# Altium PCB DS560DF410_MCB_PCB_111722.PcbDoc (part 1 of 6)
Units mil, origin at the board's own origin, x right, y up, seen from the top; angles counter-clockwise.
Board outline 5500 x 5000 mil, 6 copper layers (Top Layer, L2_GND1, L3_SIG1, L4_PWR1, L5_GND2, Bottom Layer), stack 61.748 mil thick; 297 components, 231 nets, 1236 pads, 998 vias.
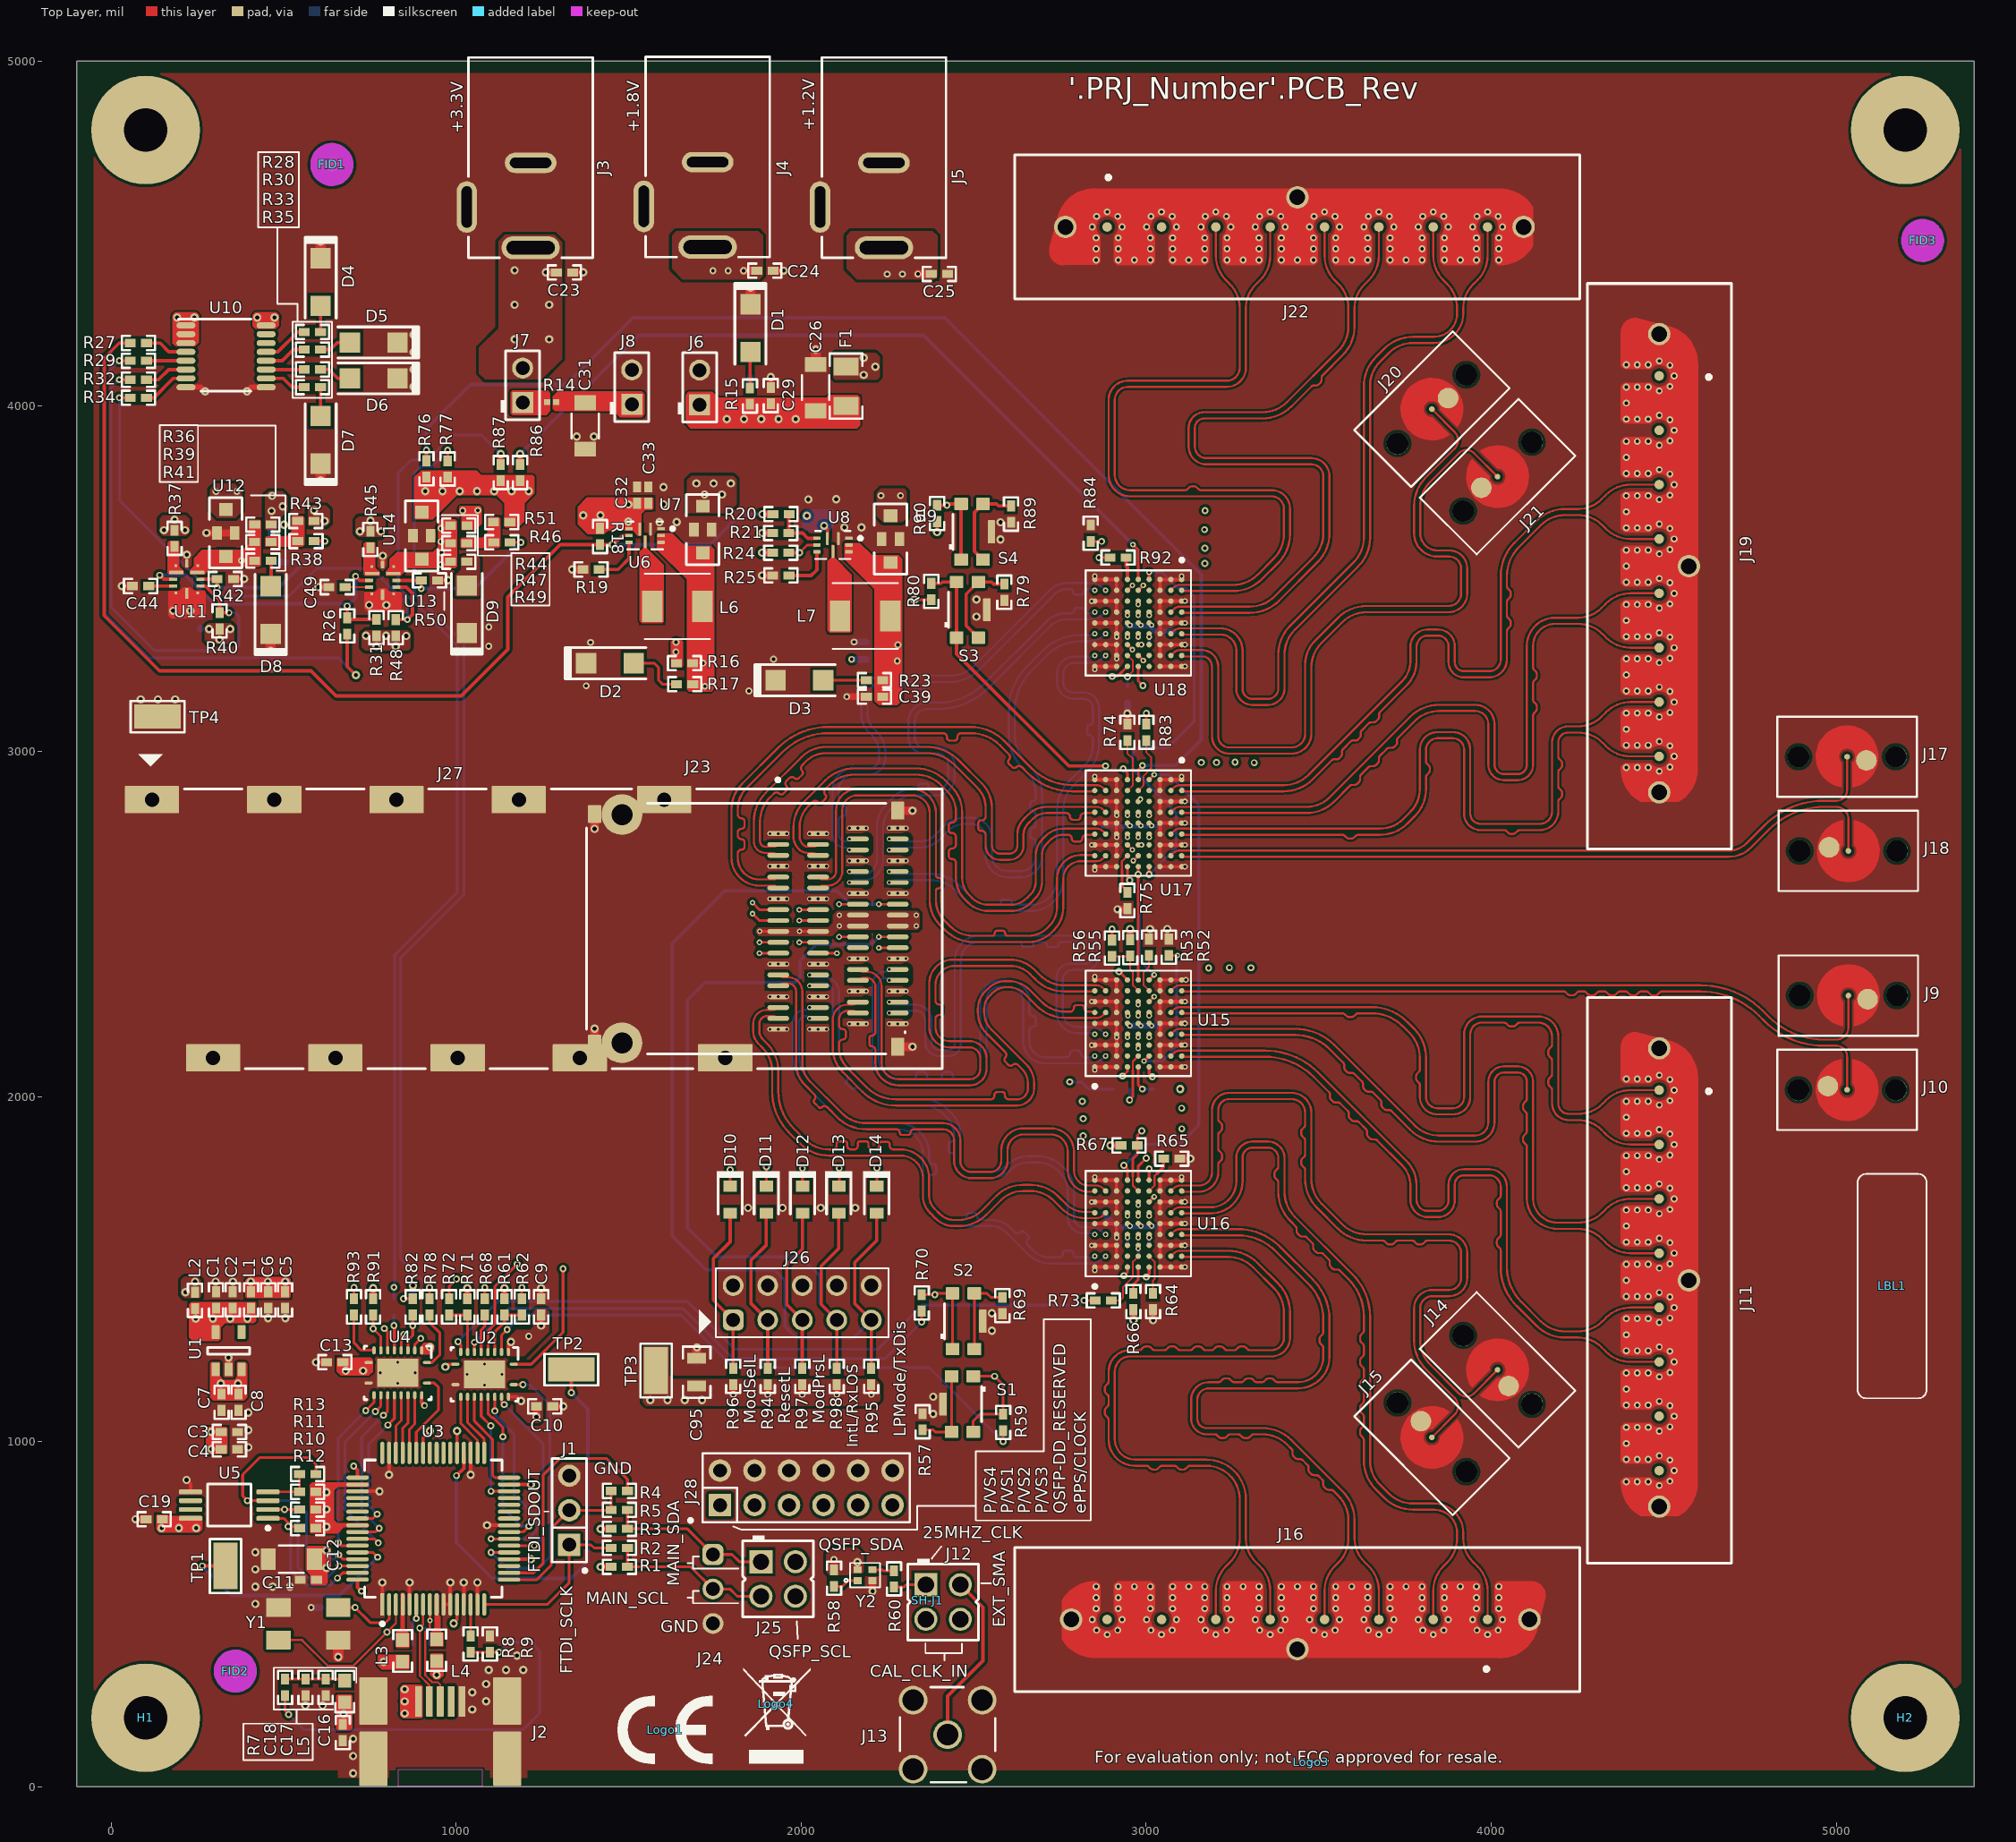
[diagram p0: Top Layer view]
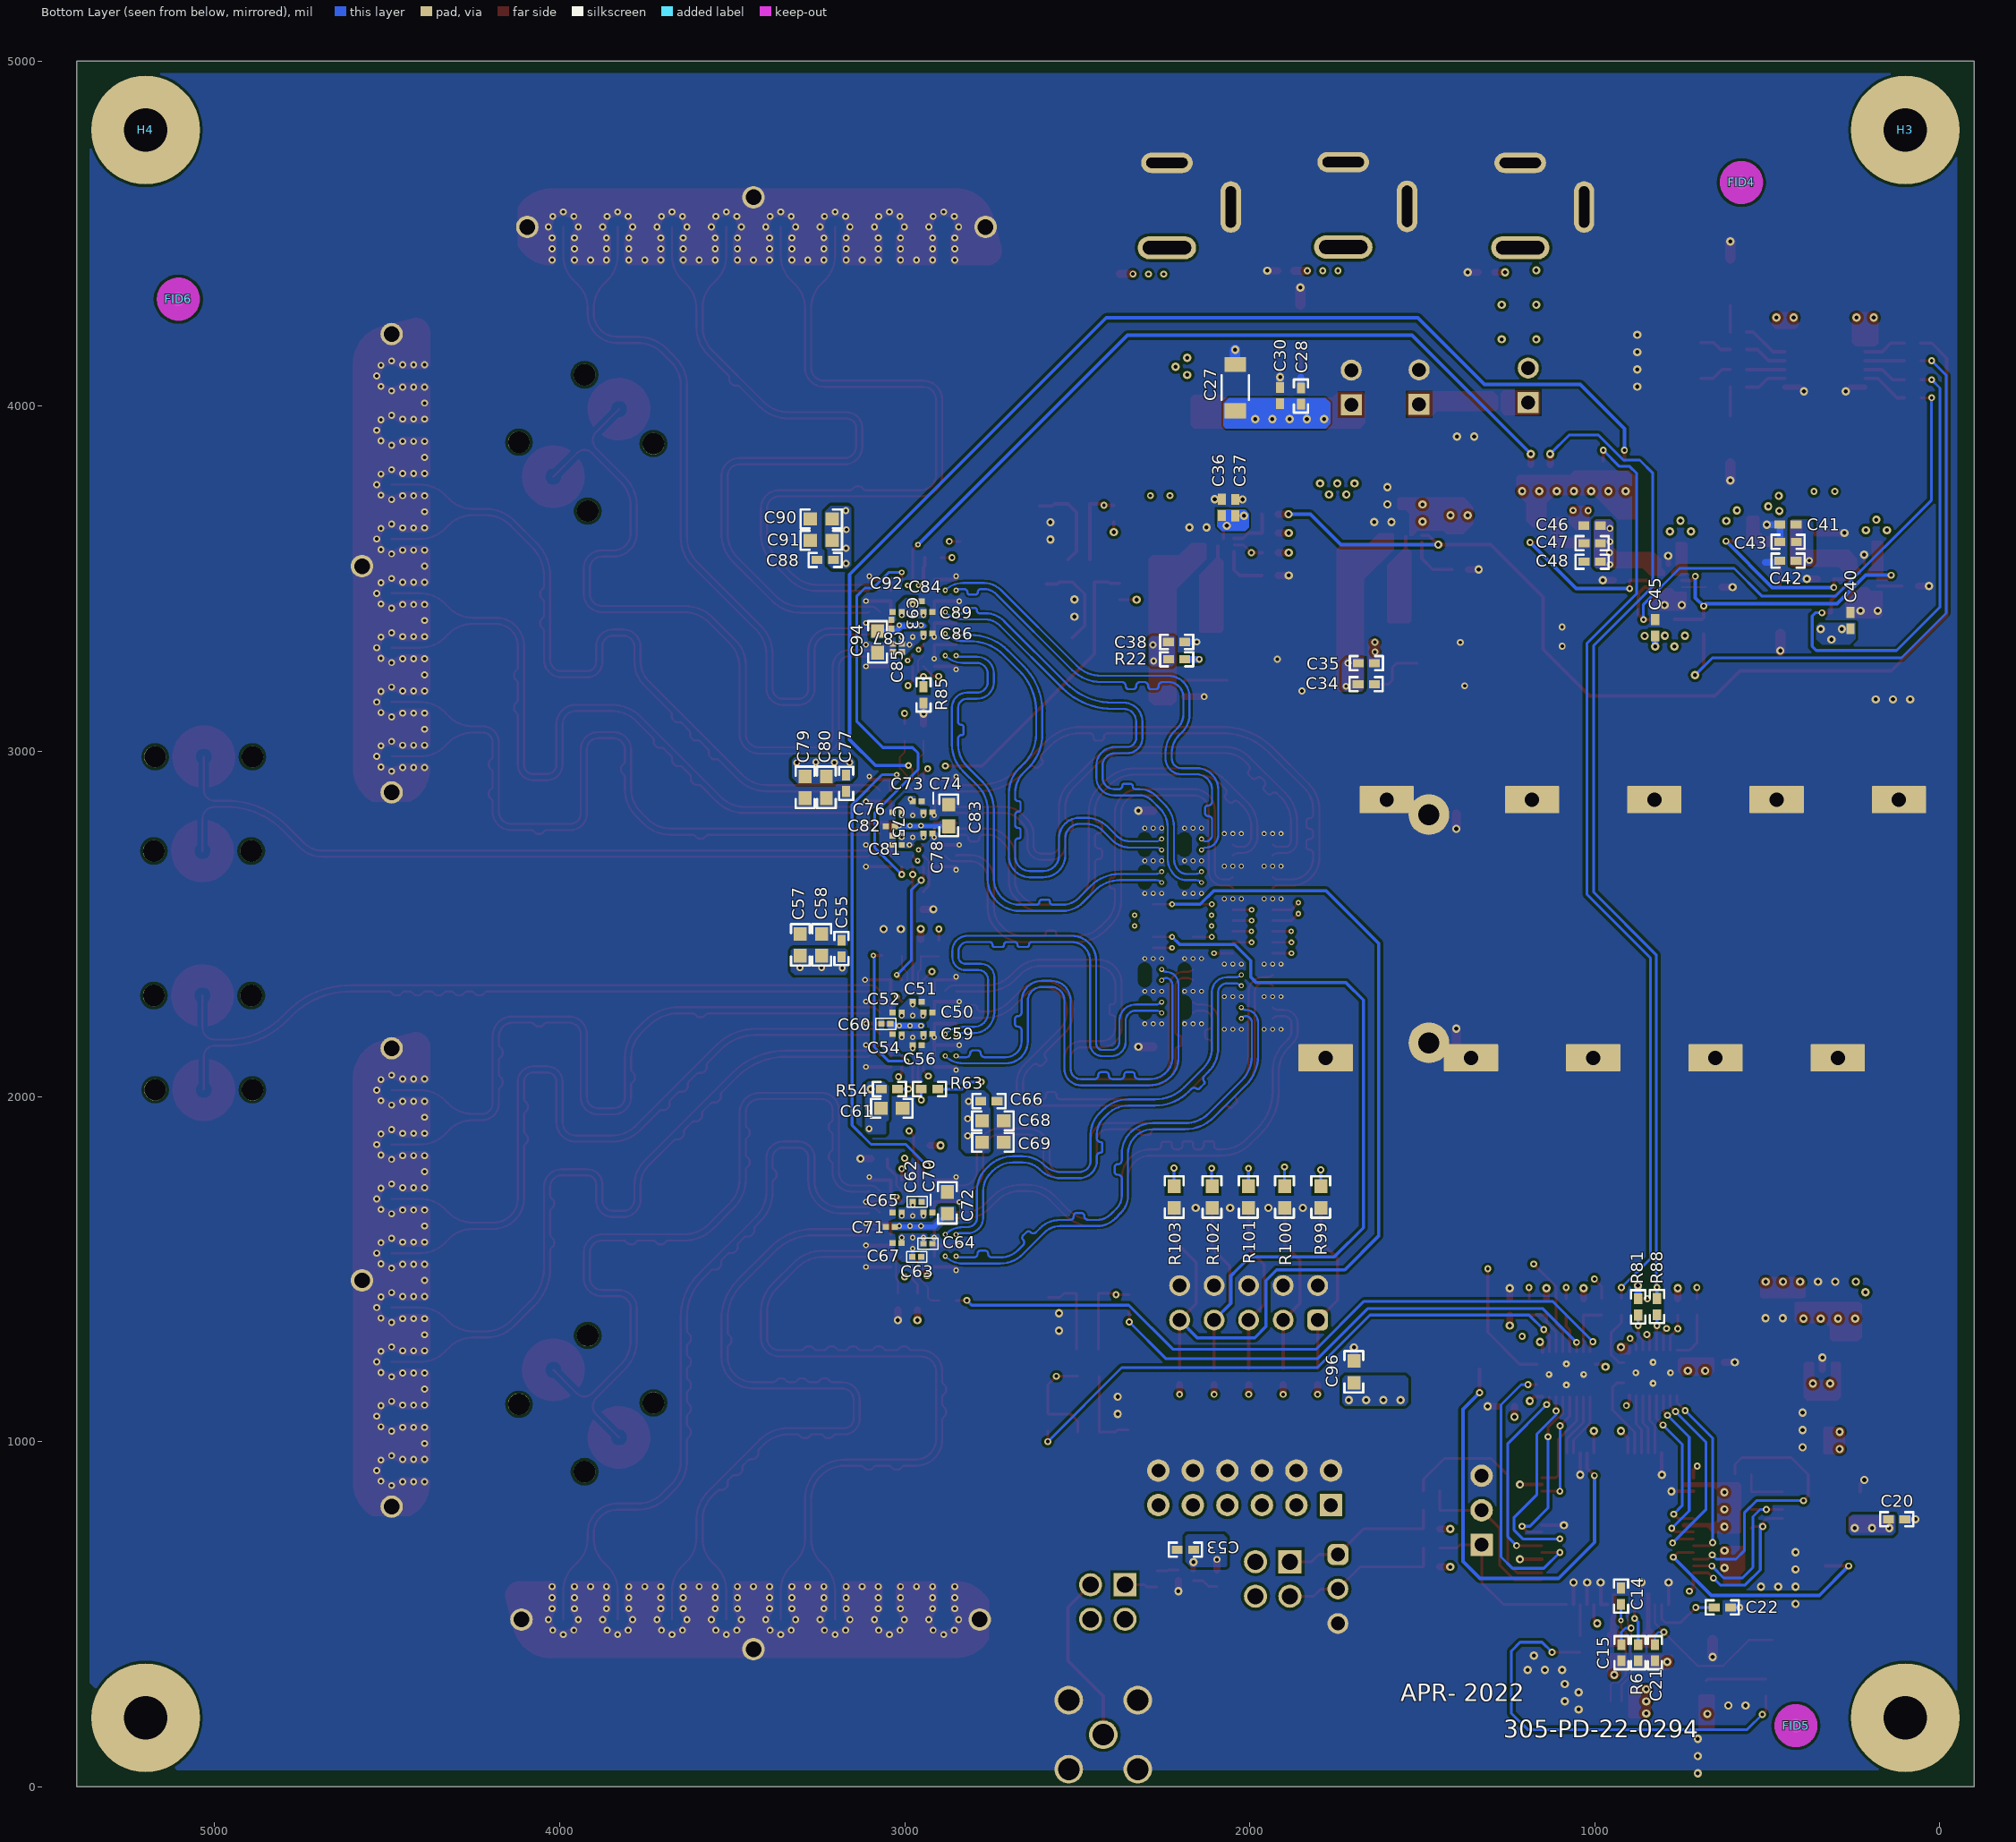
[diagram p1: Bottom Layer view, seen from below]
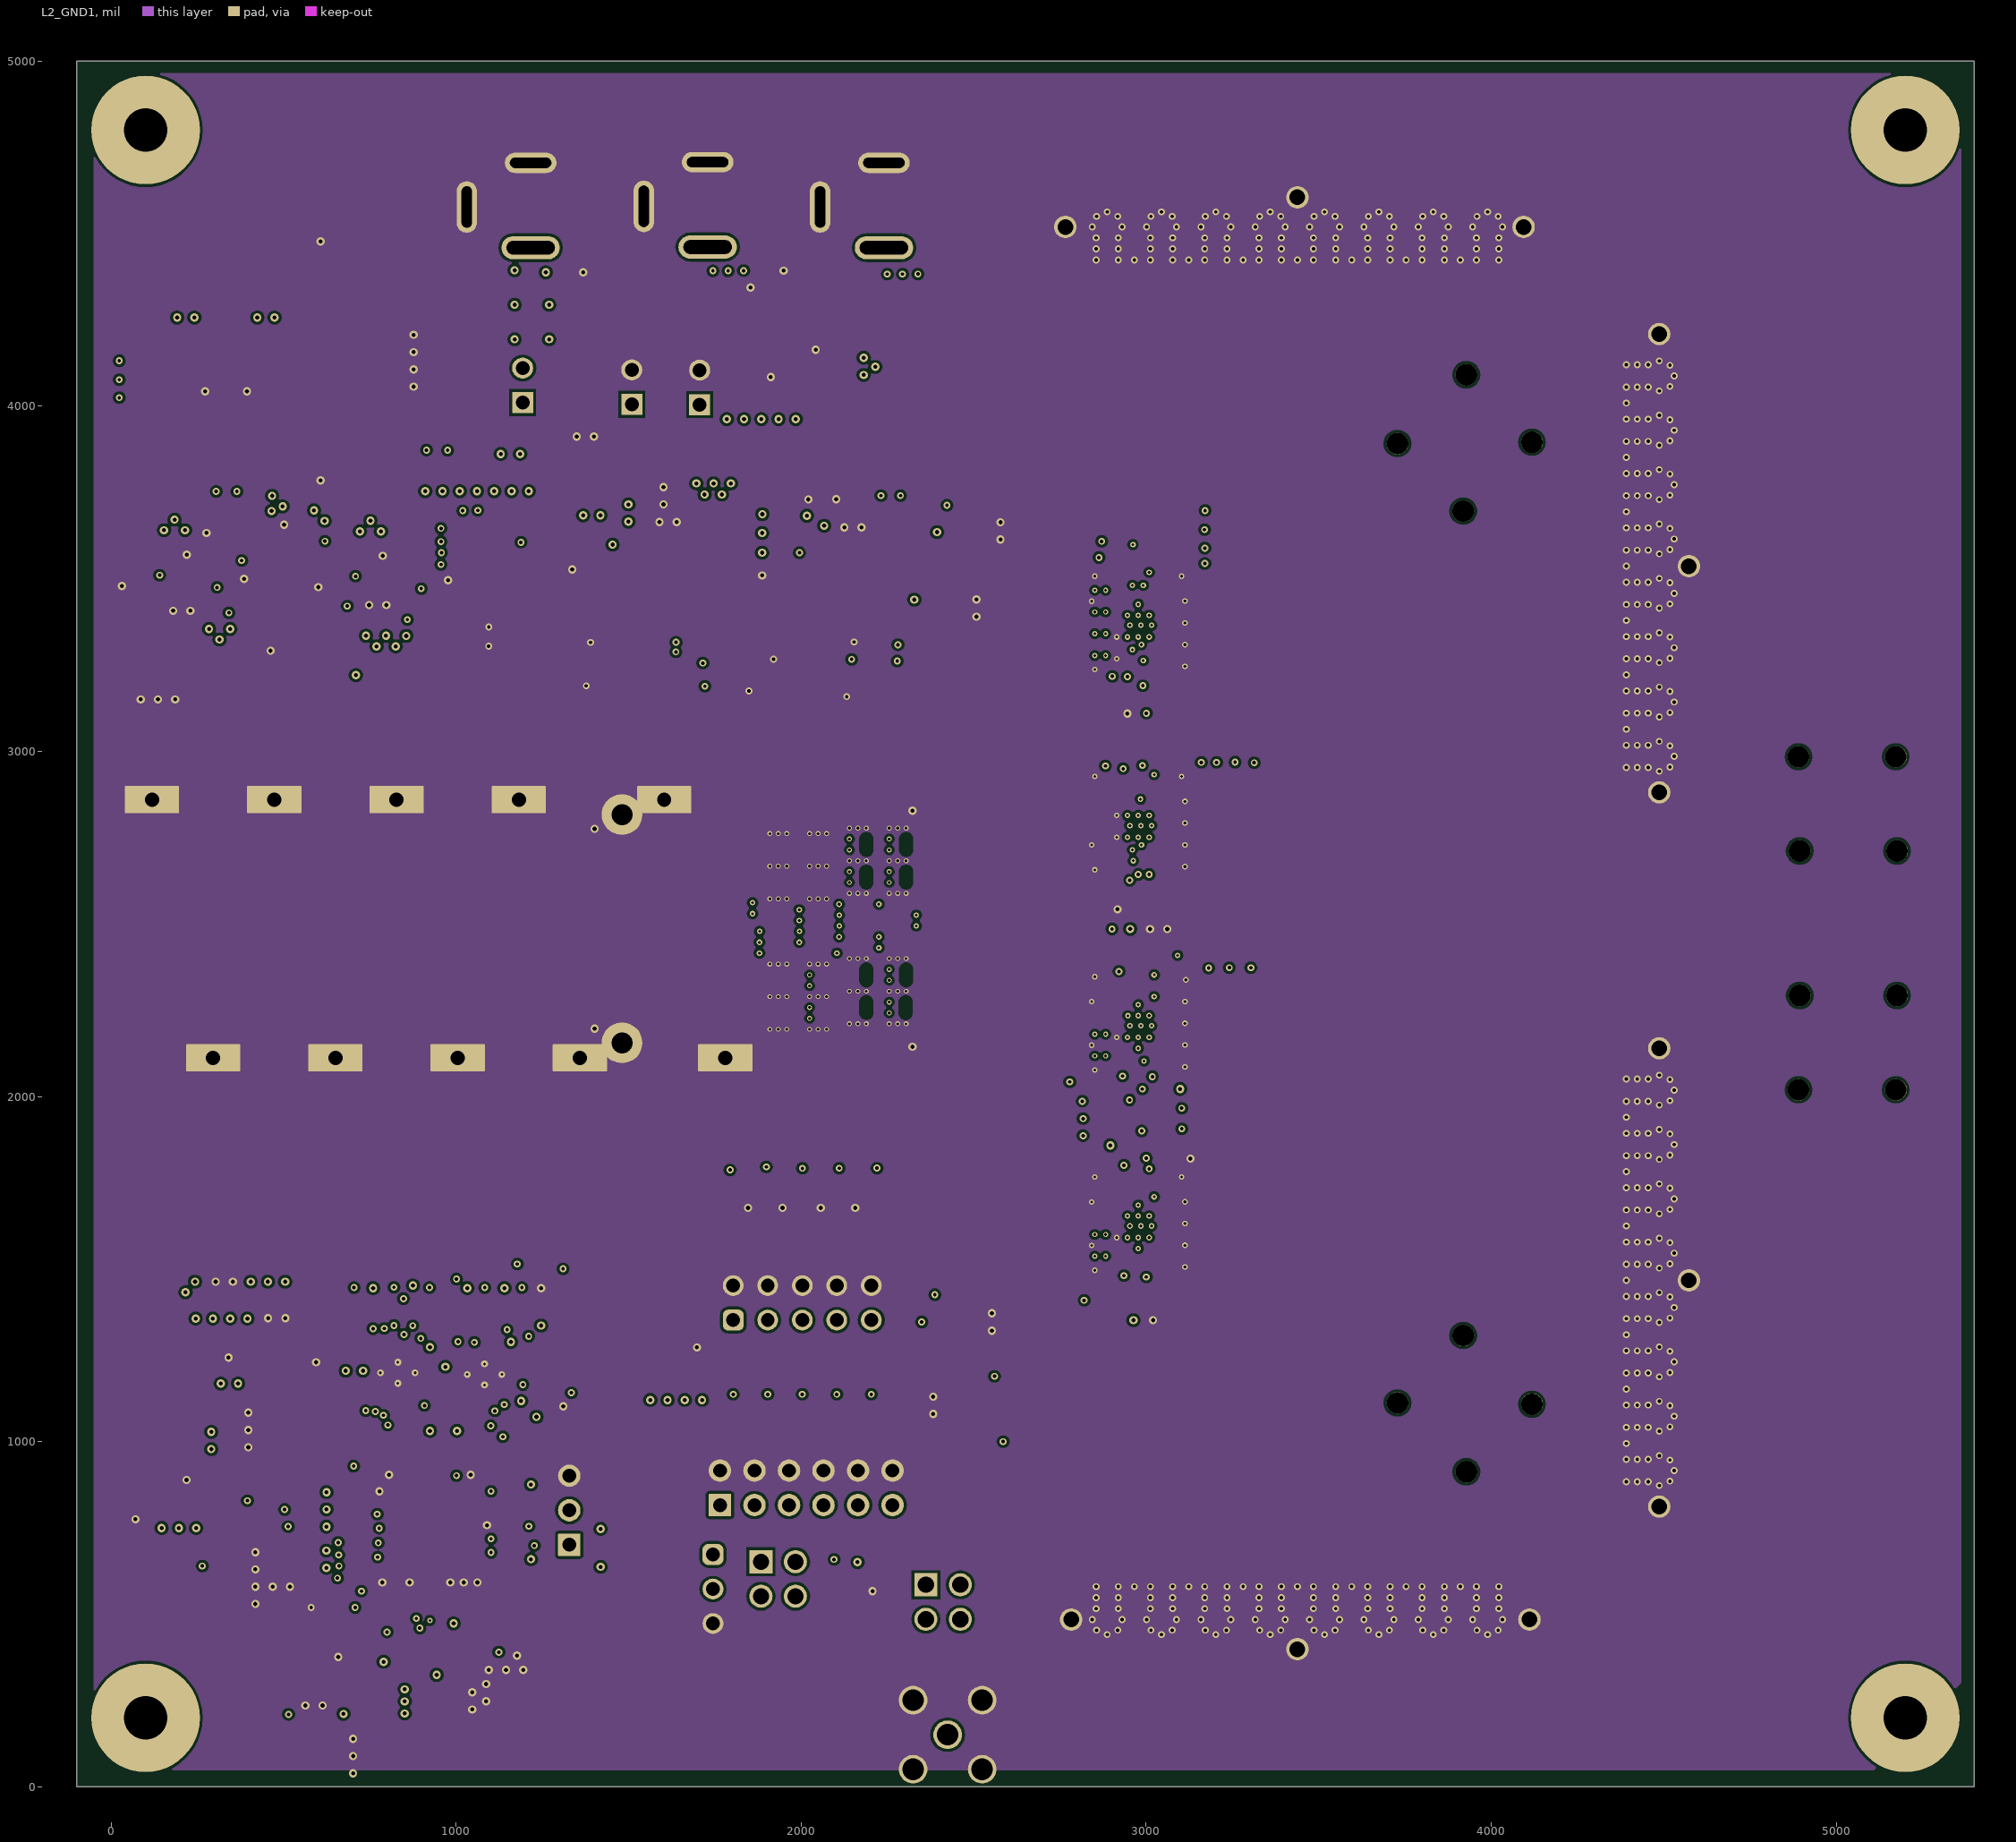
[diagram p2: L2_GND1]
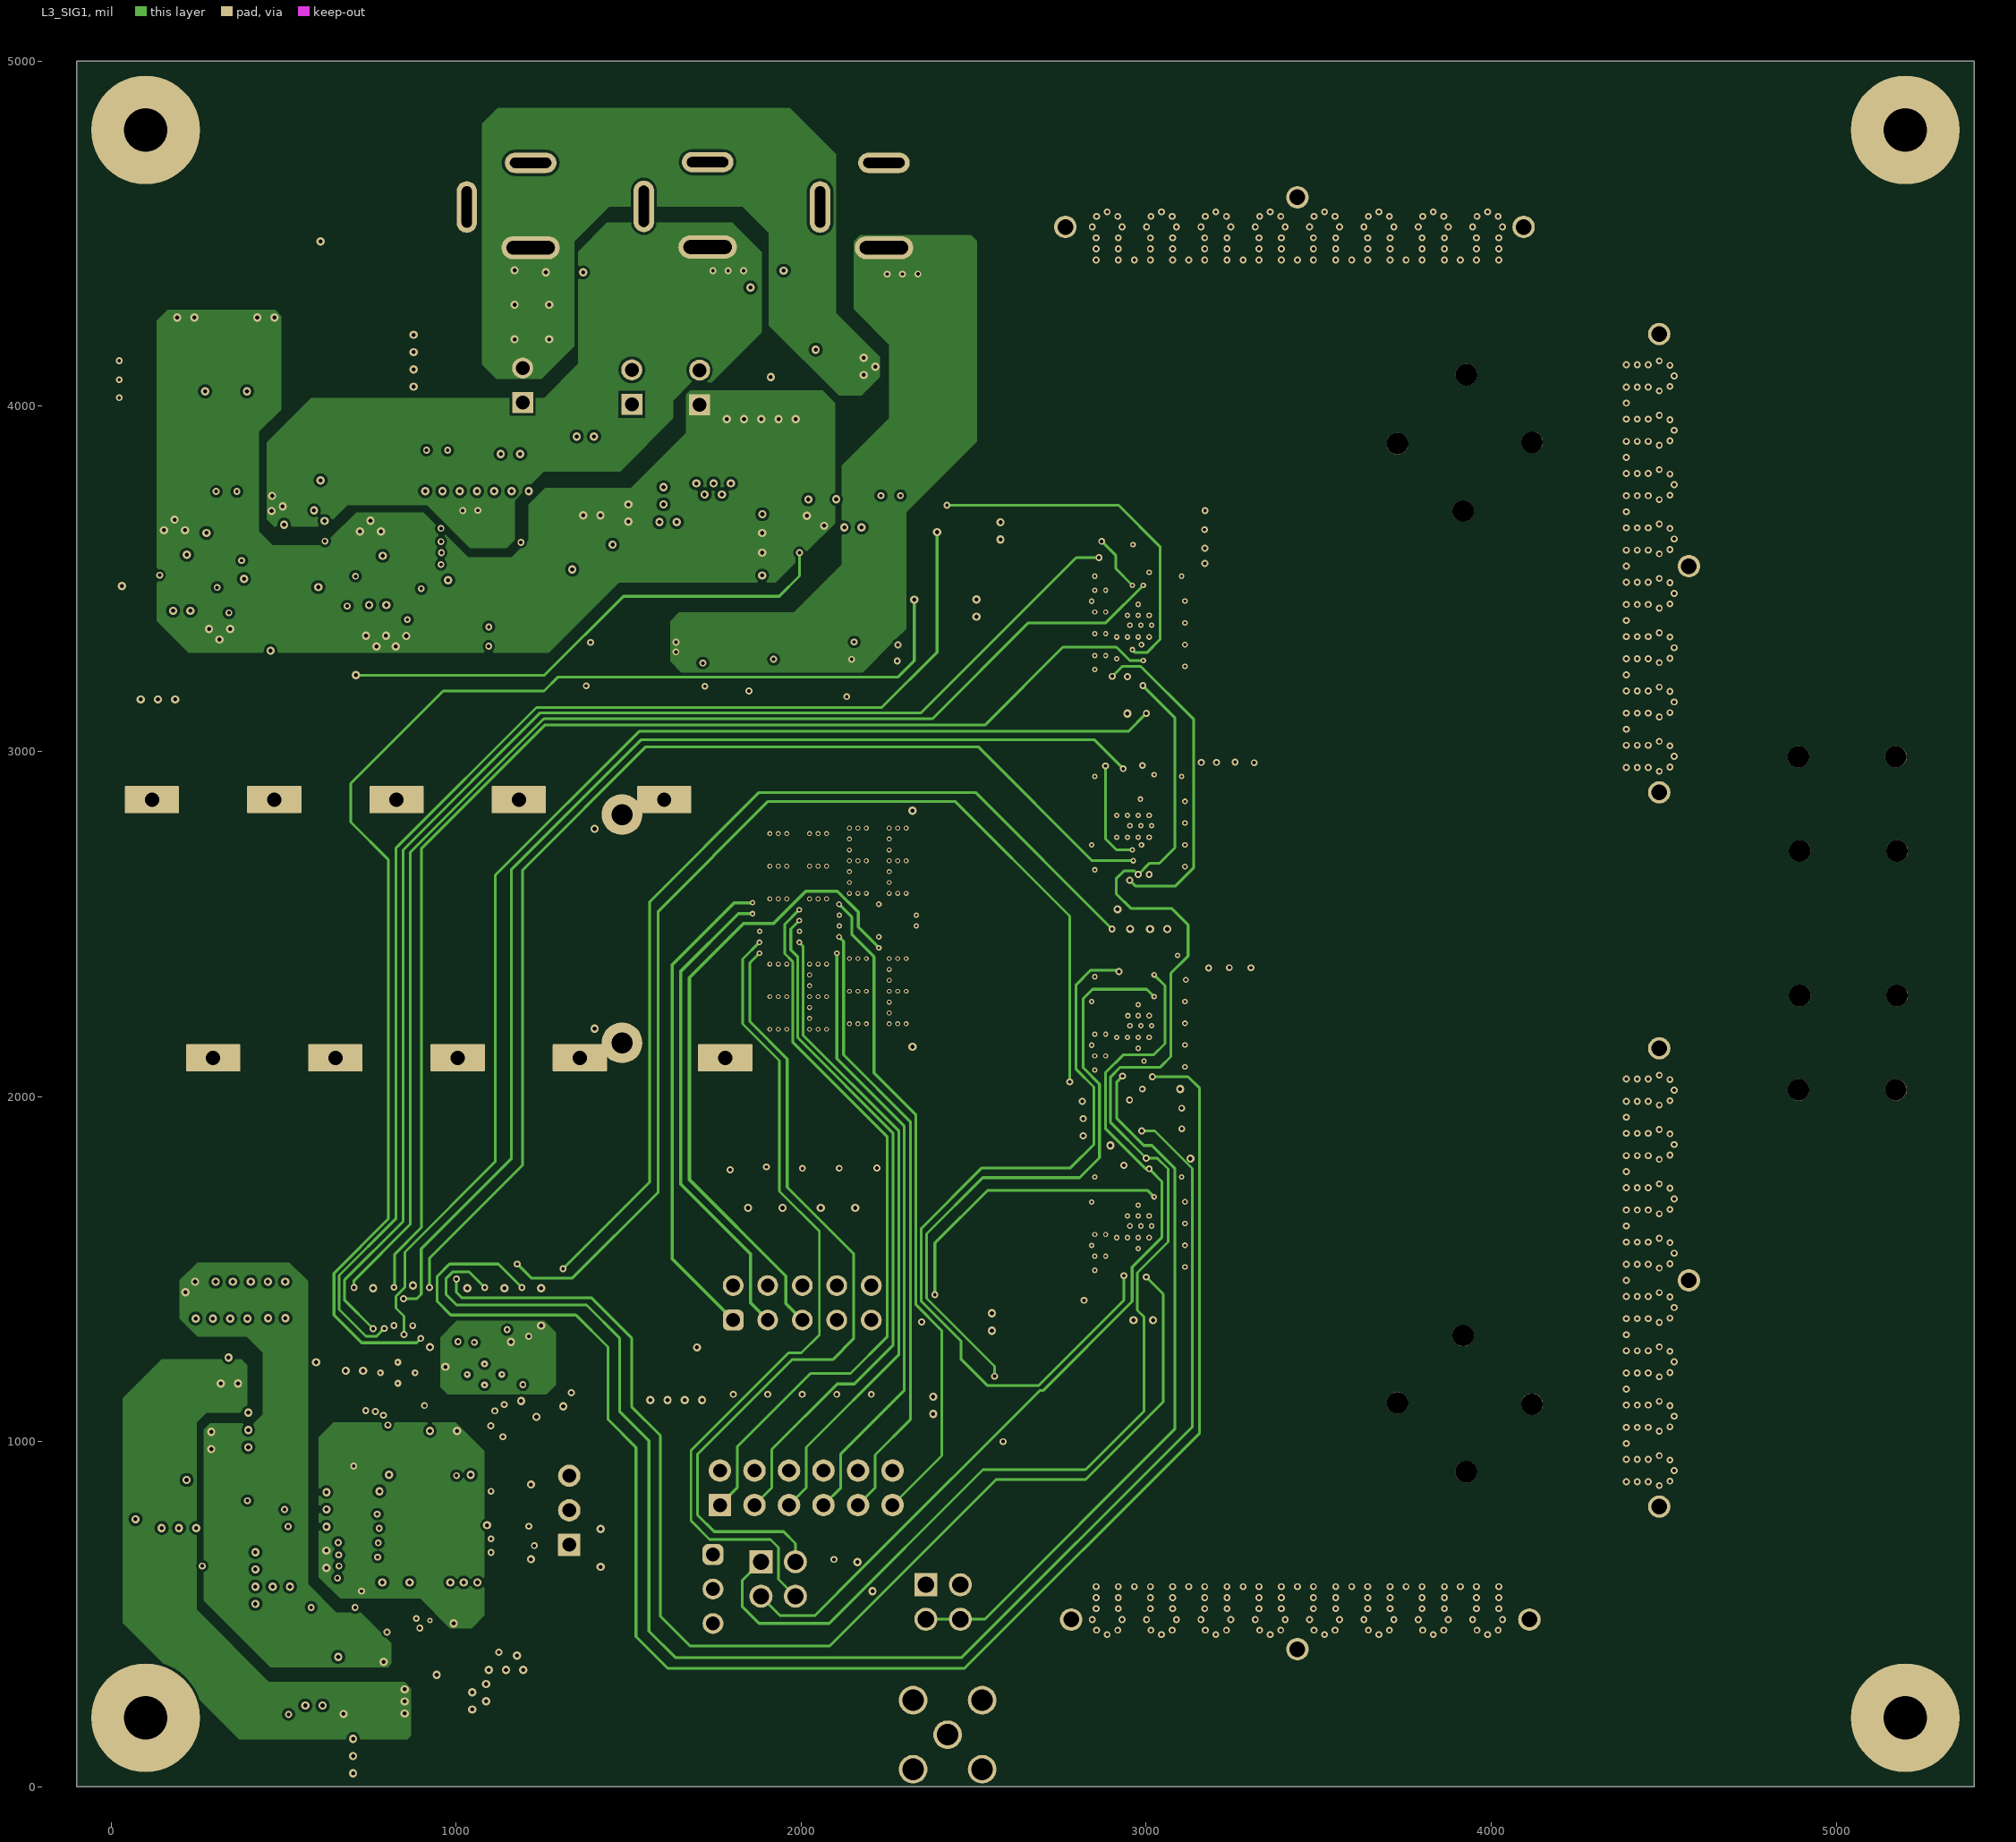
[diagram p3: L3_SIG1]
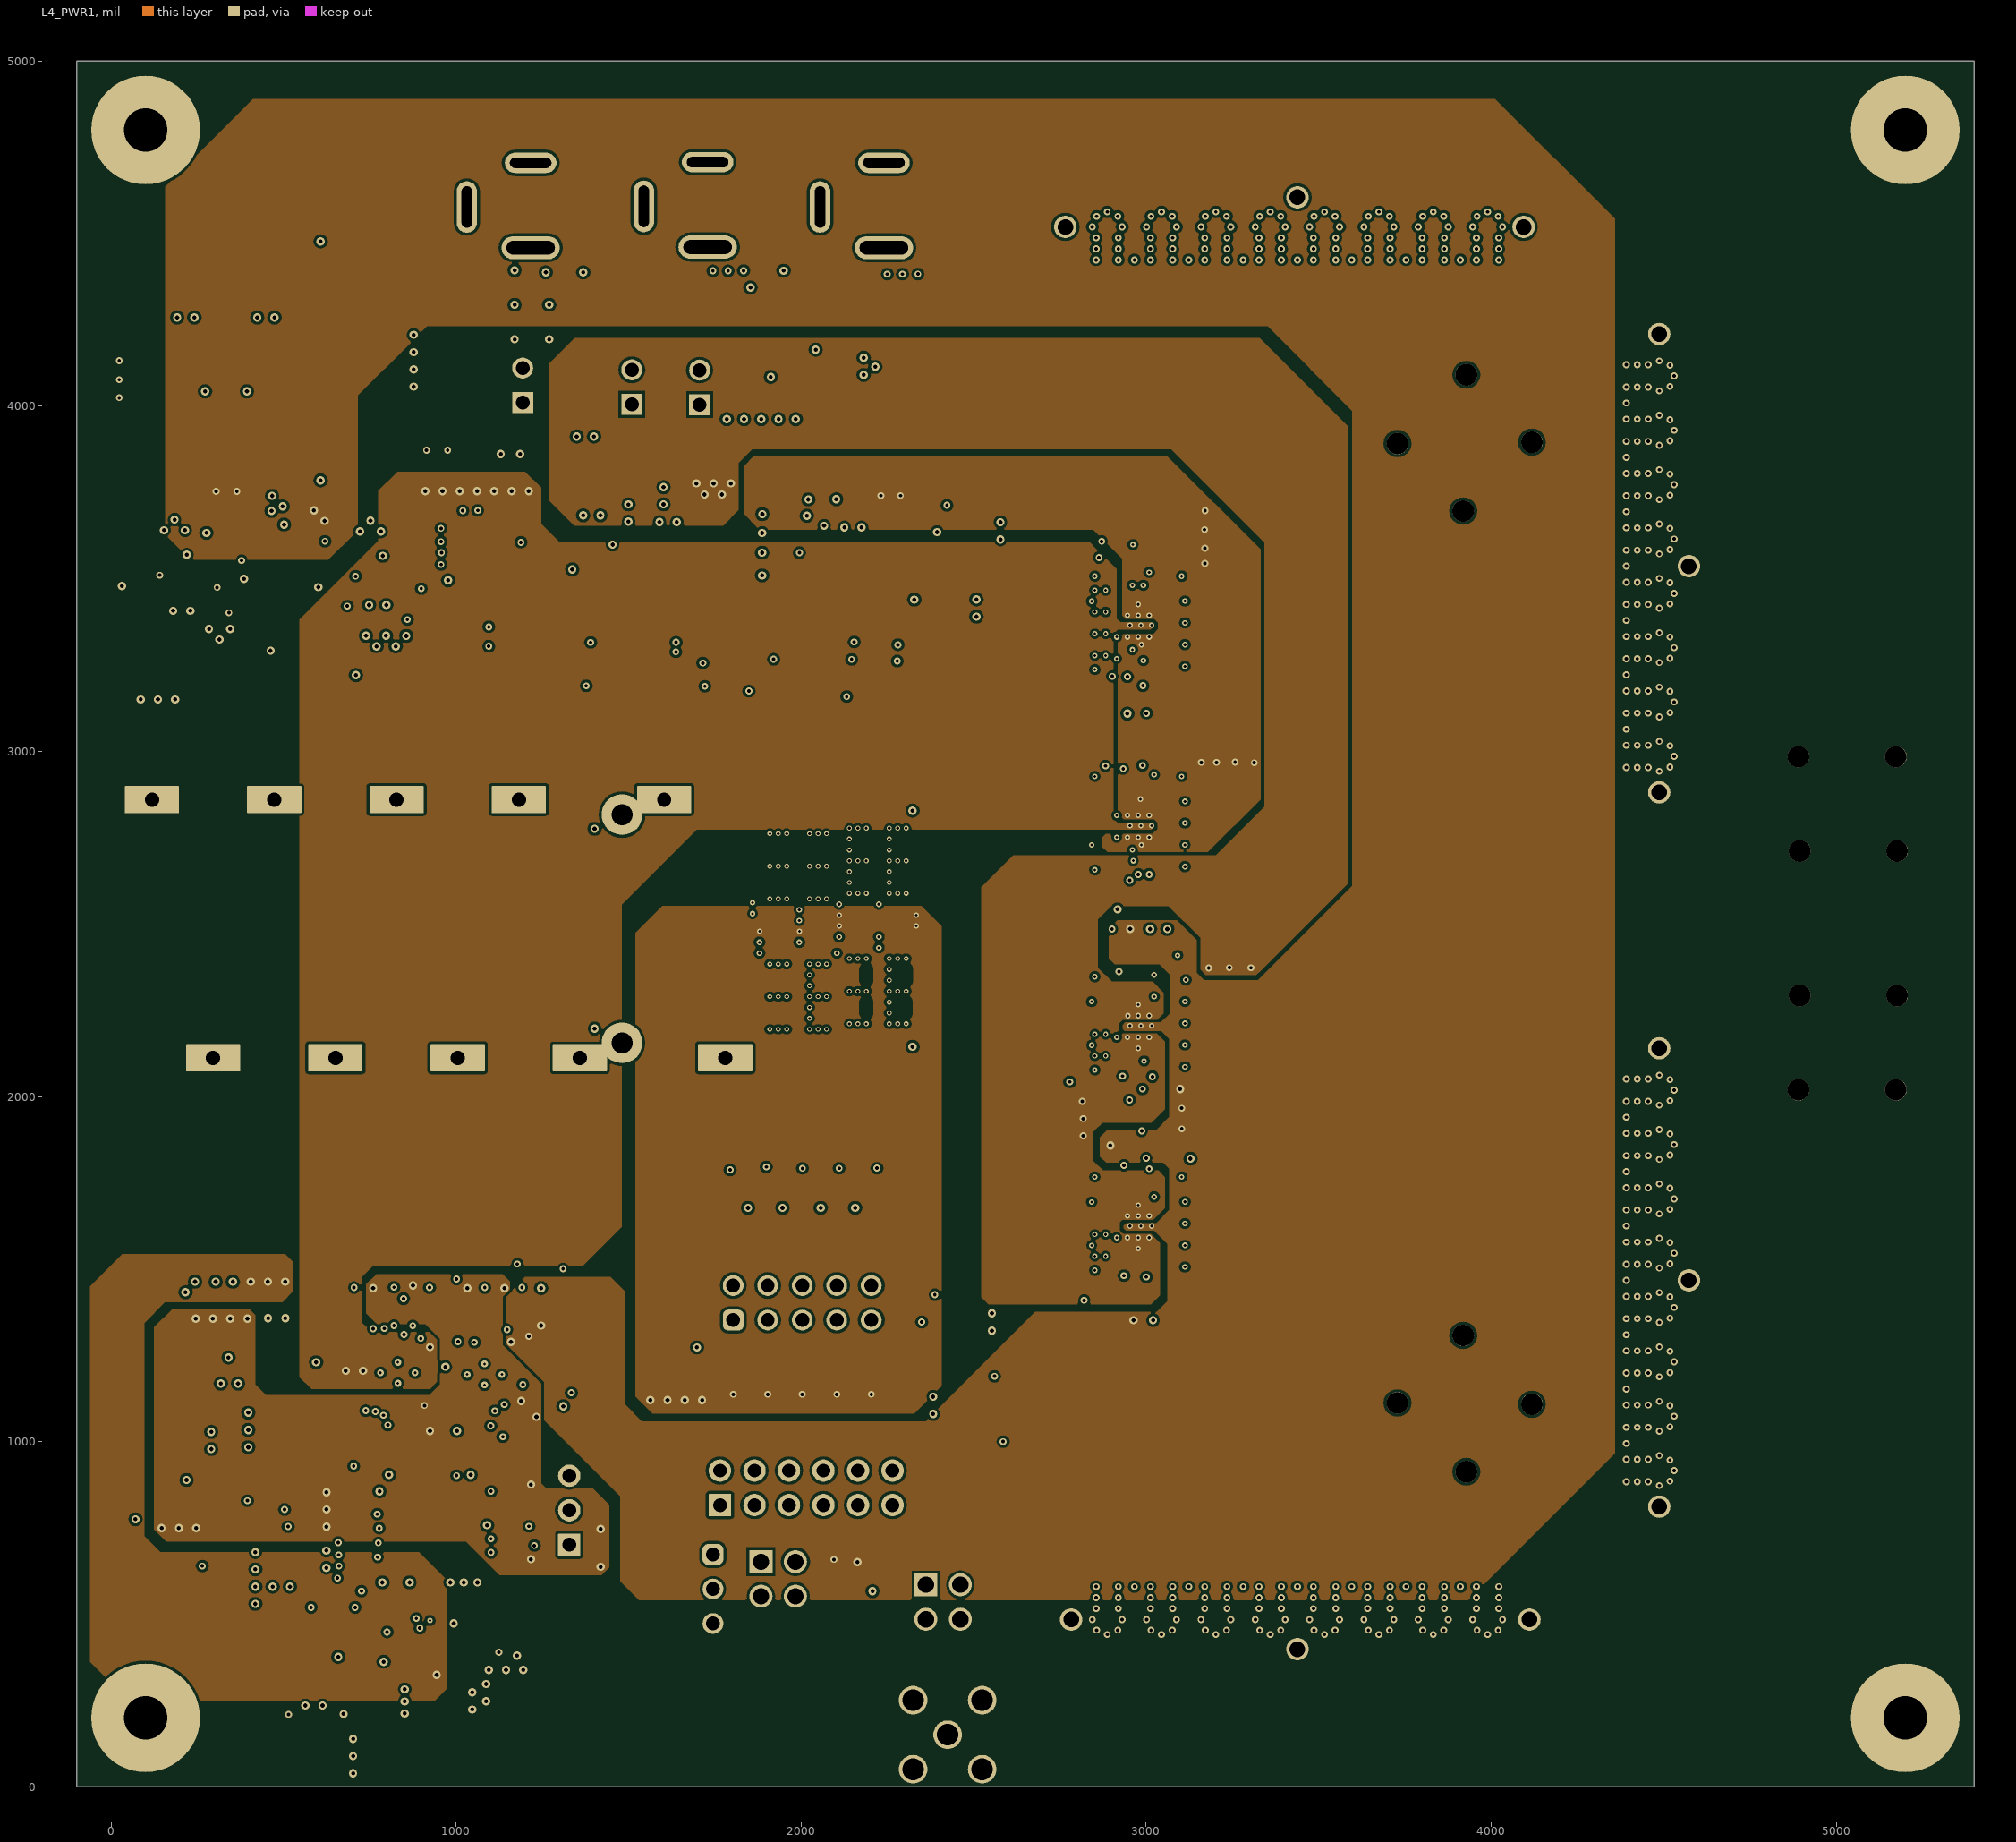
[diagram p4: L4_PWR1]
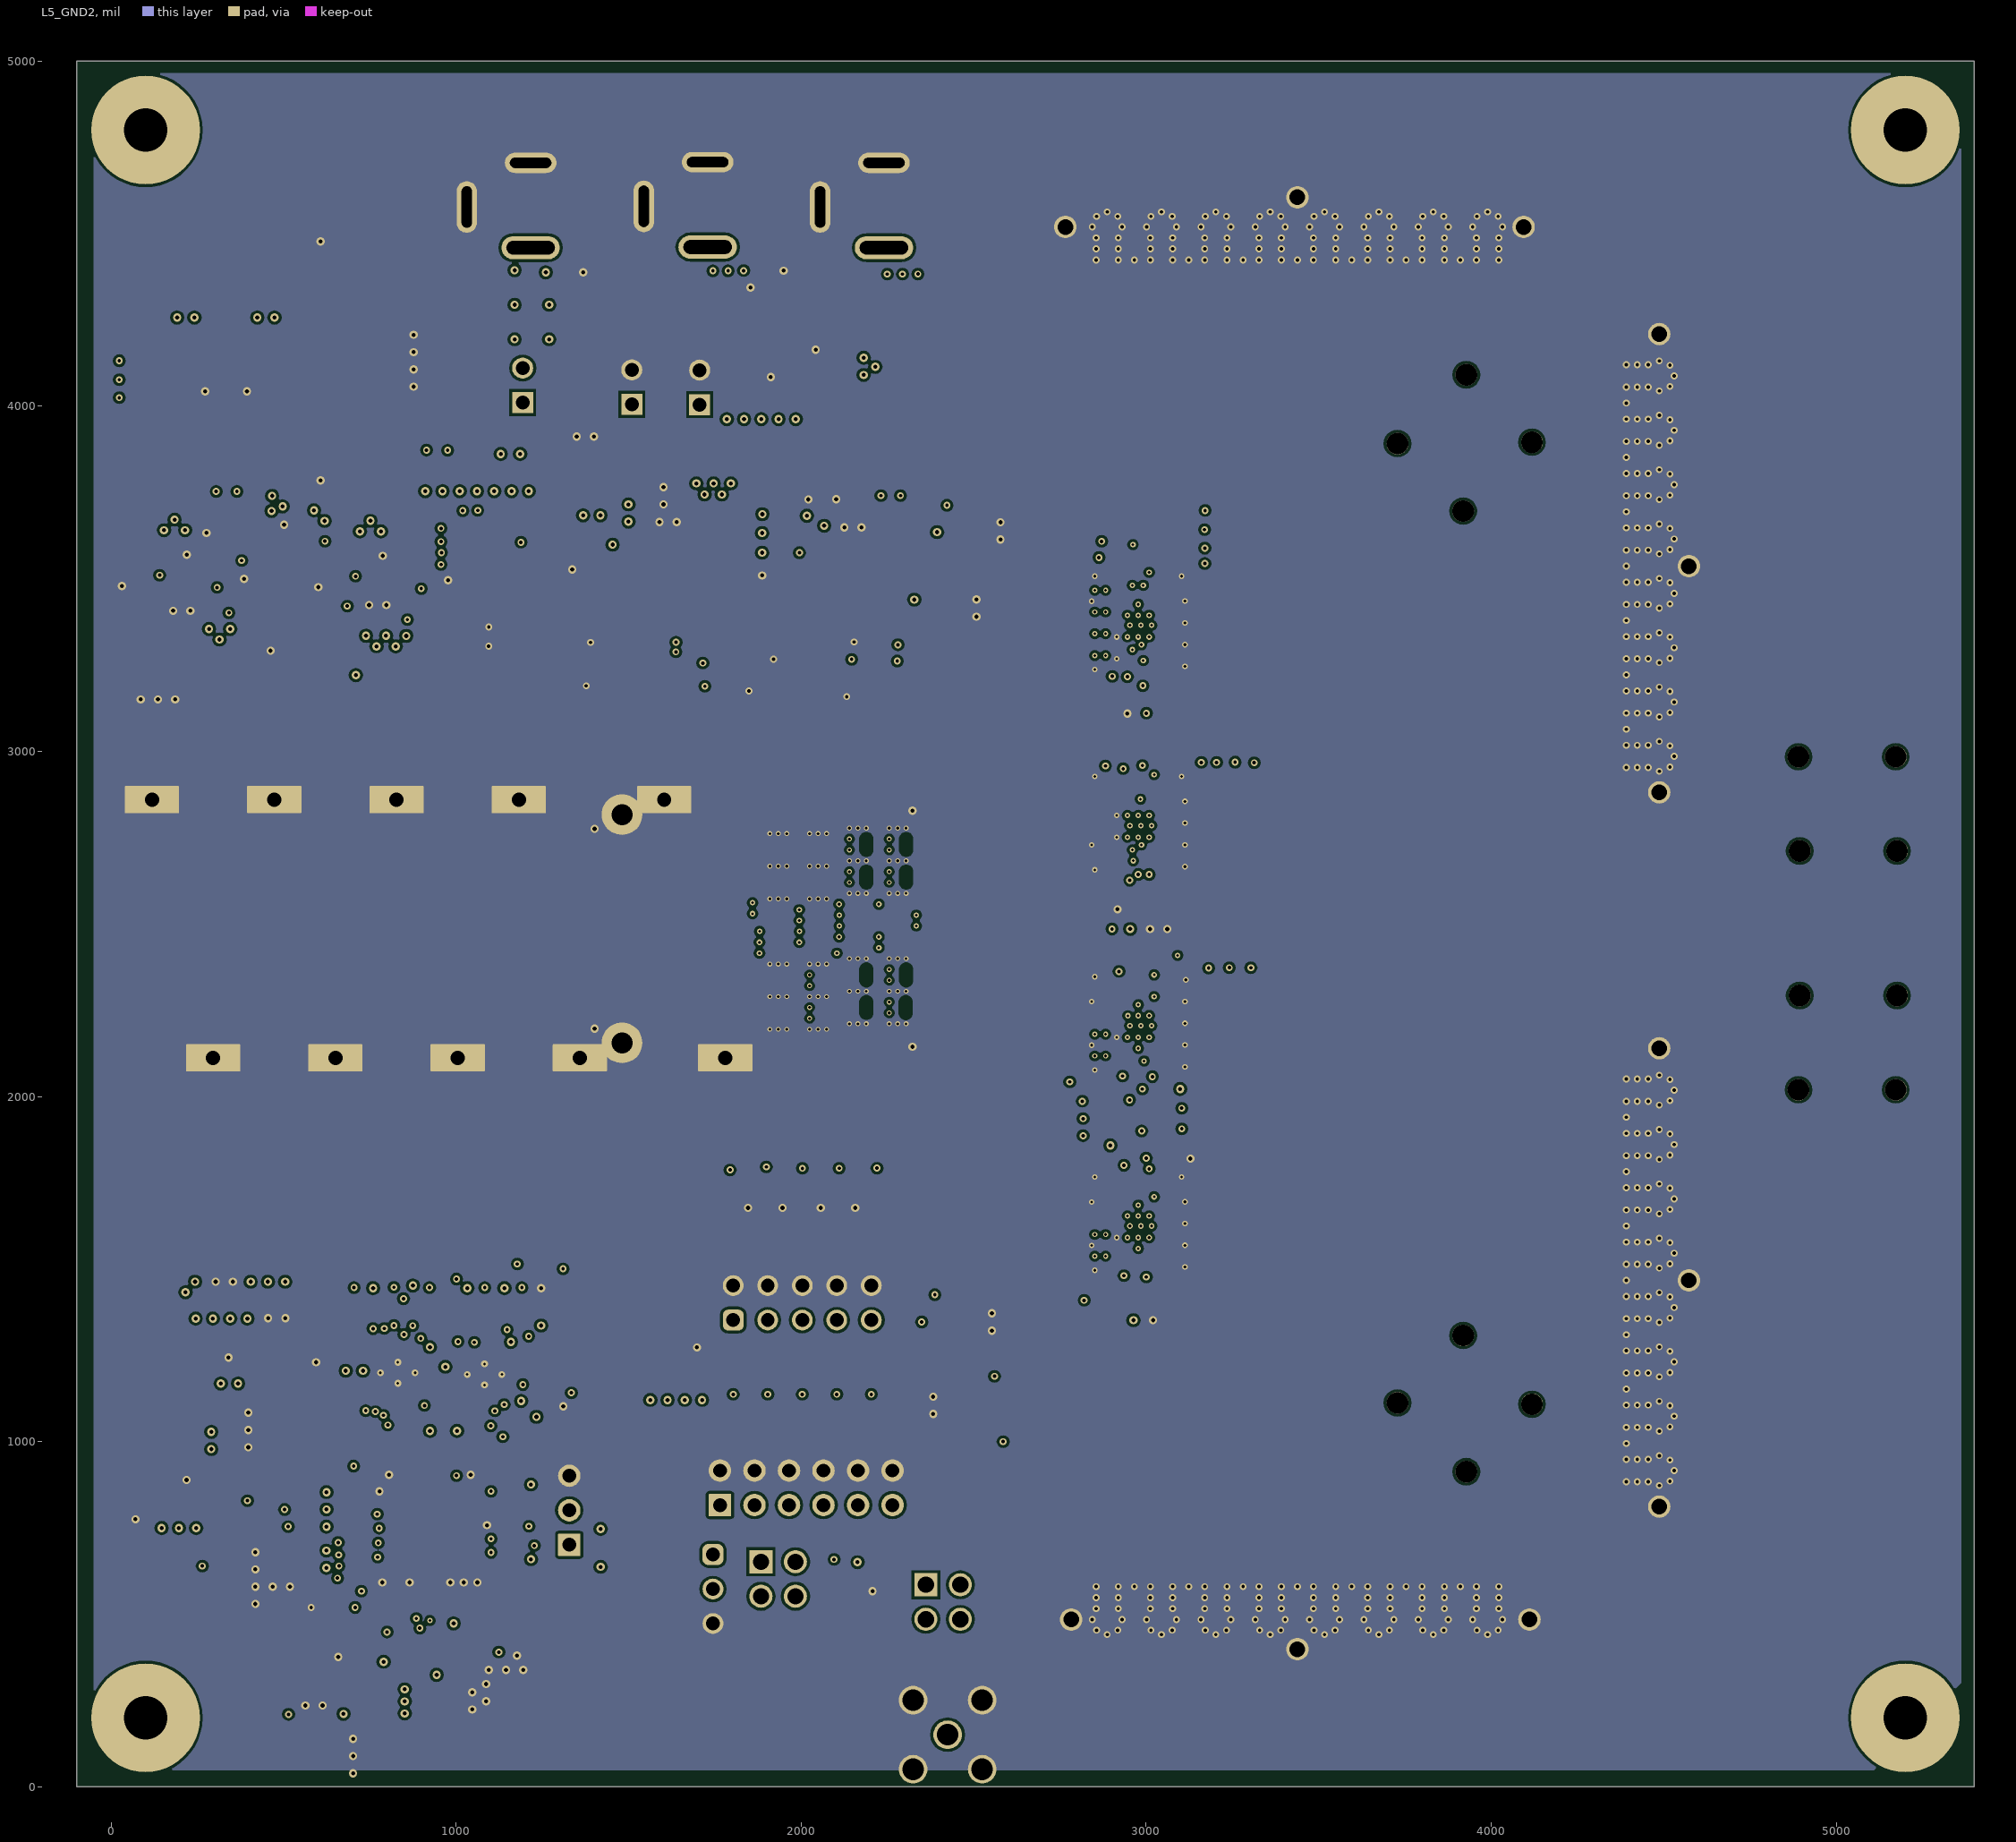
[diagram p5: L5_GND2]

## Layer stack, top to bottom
Top Solder: solder mask 0.4, Solder Resist, Dk 3.5
Top Layer: signal copper 1.4
Dielectric1: core 4.016, RO4350B, Dk 4.8
L2_GND1: signal copper 1.4
Dielectric2: prepreg 6.658, 185HR, Dk 4.2
L3_SIG1: signal copper 1.4
Dielectric3: core 31.5, 185HR, Dk 4.2
L4_PWR1: signal copper 1.4
Dielectric4: prepreg 7.158, 185HR, Dk 4.2
L5_GND2: signal copper 1.4
Dielectric5: core 4.016, RO4350B, Dk 4.2
Bottom Layer: signal copper 1.4
Bottom Solder: solder mask 0.4, Solder Resist, Dk 3.5

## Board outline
-100,0 5400,0 5400,5000 -100,5000

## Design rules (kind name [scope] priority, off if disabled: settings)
AcuteAngle [All] p1: minimum=4.50000000000000E+0001 checktracksonly=FALSE
AssemblyTestPointUsage [All] p1: valid=2
BoardOutlineClearance BoardOutlineClearance_MountingHoles [OnCopper and InComponentClass('Mounting Holes')] p1: gap=39.37 ignorepadtopadclearanceinfootprint=FALSE
BoardOutlineClearance BoardOutlineClearance_Poly [OnCopper and IsPoly] p2: gap=25 ignorepadtopadclearanceinfootprint=FALSE
BoardOutlineClearance [OnCopper and Not InComponentClass('Logo') and not InComponentClass('FiducialMark') and not InRegion(1000,500,4000,800) and not InPoly] p3: gap=75 ignorepadtopadclearanceinfootprint=FALSE
Clearance Clearance_3 [InNetClass('HS')] p1: gap=10 ignorepadtopadclearanceinfootprint=TRUE except(4: Via-Region; 4.8: Arc-Arc Arc-Track Arc-SMDPad Track-Track Track-SMDPad; 5.4: SMDPad-Via; 5.6: Arc-Via Track-Via; 6: Arc-Poly Track-Poly; 7: Region-Hole; 8: Arc-Hole Track-Hole SMDPad-Hole THPad-Hole Via-Hole Fill-Hole Poly-Hole Text-Hole; 20: Poly-Poly)
Clearance Clearance_4 [(AsMils(Width) = 6.4)] p2: gap=10 ignorepadtopadclearanceinfootprint=TRUE except(4: Via-Region; 5.4: SMDPad-Via; 6: Arc-Arc Arc-Track Arc-Via Arc-Poly Track-Track Track-Via Track-Poly; 7: Region-Hole; 8: Arc-SMDPad Arc-Hole Track-SMDPad Track-Hole SMDPad-Hole THPad-Hole Via-Hole Fill-Hole Poly-Hole Text-Hole; 20: Poly-Poly)
Clearance Clearance_5 [(AsMils(Width) = 6)] p3: gap=10 ignorepadtopadclearanceinfootprint=TRUE except(4: Via-Region; 4.8: Arc-Arc Arc-Track Arc-SMDPad Track-Track Track-SMDPad; 5.4: SMDPad-Via; 6: Arc-Via Arc-Poly Track-Via Track-Poly; 7: Region-Hole; 8: Arc-Hole Track-Hole SMDPad-Hole THPad-Hole Via-Hole Fill-Hole Poly-Hole Text-Hole; 20: Poly-Poly)
Clearance Clearance_6 [(AsMils(Width) = 7)] p4: gap=10 ignorepadtopadclearanceinfootprint=TRUE except(4: Via-Region; 5.4: SMDPad-Via; 6: Arc-Arc Arc-Track Arc-Via Track-Track Track-Via; 7: Region-Hole; 8: Arc-SMDPad Arc-Poly Arc-Hole Track-SMDPad Track-Poly Track-Hole SMDPad-Hole THPad-Hole Via-Hole Fill-Hole Poly-Hole Text-Hole; 20: Poly-Poly)
Clearance Clearance_1 [WithinRoom('QSFP-DD_Connector')] p5: gap=3 ignorepadtopadclearanceinfootprint=TRUE
Clearance Clearance_2 [WithinRoom('PWR_2P5V_DCDC_EEPROM')] p6: gap=3 ignorepadtopadclearanceinfootprint=TRUE
Clearance Clearance_Keepouts [((IsTrack Or IsArc) And Not InPoly) And IsFree and IsKeepOut vs ((IsTrack Or IsArc) And Not InPoly) And IsFree and IsKeepOut] p7: gap=0 ignorepadtopadclearanceinfootprint=FALSE
Clearance Clearance_FiducialMark [IsKeepOut and InComponentClass('FiducialMark') vs IsPad and InComponentClass('FiducialMark')] p8: gap=0 ignorepadtopadclearanceinfootprint=FALSE
Clearance [All] p9: gap=8 ignorepadtopadclearanceinfootprint=TRUE except(4.8: Arc-Arc Arc-Track Arc-SMDPad Track-SMDPad SMDPad-Via; 5: Track-Region SMDPad-Region Via-Region Poly-Region Region-Region; 5.6: Track-Via; 7: Track-Track; 9.8: SMDPad-SMDPad)
ComponentClearance ComponentClearance_MountingHoles_FiducialMarks [InComponentClass('Mounting Holes') vs InComponentClass('FiducialMark')] p1: gap=50 collisioncheckmode=3 verticalgap=10 showdistances=FALSE
ComponentClearance ComponentClearance_Shunt [InComponentClass('Header') vs InComponentClass('Shunt')] p2: gap=0 collisioncheckmode=3 verticalgap=0 showdistances=FALSE
ComponentClearance ComponentClearance_Logo [InComponentClass('Logo')] p3: gap=5 collisioncheckmode=3 verticalgap=5 showdistances=FALSE
ComponentClearance ComponentClearance_ScrewToNut [(HasFootprint('NY PMS 440 0025 PH')) vs (HasFootprint('Keystone_1902C'))] p4: gap=5 collisioncheckmode=3 verticalgap=10 showdistances=FALSE
ComponentClearance ComponentClearance_MountingHoles [InComponentClass('Mounting Holes')] p5: gap=50 collisioncheckmode=3 verticalgap=100000 showdistances=FALSE
ComponentClearance ComponentClearance_SmallPassives [HasFootprint('0201*') or HasFootprint('0402*') or HasFootprint('0508') or HasFootprint('0603*') or HasFootprint('0612') or HasFootprint('0805*') or HasFootprint('0815*') or HasFootprint('0830*') or HasFootprint('1206*') or HasFootprint('1210*') or HasFootprint('1808*') or HasFootprint('1812*') or HasFootprint('1825*') or HasFootprint('2010*') or HasFootprint('2220*') or HasFootprint('2225*') or HasFootprint('2512*') or HasFootprint('2728*') or HasFootprint('3518*') vs HasFootprint('0201*') or HasFootprint('0402*') or HasFootprint('0508') or HasFootprint('0603*') or HasFootprint('0612') or HasFootprint('0805*') or HasFootprint('0815*') or HasFootprint('0830*') or HasFootprint('1206*') or HasFootprint('1210*') or HasFootprint('1808*') or HasFootprint('1812*') or HasFootprint('1825*') or HasFootprint('2010*') or HasFootprint('2220*') or HasFootprint('2225*') or HasFootprint('2512*') or HasFootprint('2728*') or HasFootprint('3518*')] p6: gap=5 collisioncheckmode=3 verticalgap=5 showdistances=FALSE
ComponentClearance ComponentClearance_THtoSMT [IsThruComponent vs IsSMTComponent] p7: gap=5 collisioncheckmode=3 verticalgap=5 showdistances=FALSE
ComponentClearance ComponentClearance_THtoTH [IsThruComponent vs IsThruComponent] p8: gap=30 collisioncheckmode=3 verticalgap=30 showdistances=FALSE
ComponentClearance [All] p9: gap=5 collisioncheckmode=3 verticalgap=5 showdistances=FALSE
DiffPairsRouting DiffPairsRouting_1 [InDifferentialPairClass('90ohm')] p1: maxlimit=10 minlimit=8 mostfreqgap=10 toplayer_maxgap=8 toplayer_prefgap=8 toplayer_minwidth=7 toplayer_maxwidth=7 toplayer_prefwidth=7 midlayer1_mingap=10 midlayer1_minwidth=15 midlayer1_maxwidth=15 midlayer1_prefwidth=15 midlayer2_mingap=10 midlayer2_minwidth=15 midlayer2_maxwidth=15 midlayer2_prefwidth=15 midlayer3_mingap=10 midlayer3_minwidth=15 midlayer3_maxwidth=15 midlayer3_prefwidth=15 midlayer4_mingap=10 midlayer4_minwidth=15 midlayer4_maxwidth=15 midlayer4_prefwidth=15 bottomlayer_maxgap=8 bottomlayer_prefgap=8 bottomlayer_minwidth=7 bottomlayer_maxwidth=7 bottomlayer_prefwidth=7 maxuncoupledlength=500
DiffPairsRouting [All] p2: maxlimit=12 minlimit=12 mostfreqgap=12 toplayer_minwidth=6 toplayer_maxwidth=6.4 toplayer_prefwidth=6 midlayer1_minwidth=6 midlayer1_maxwidth=6 midlayer1_prefwidth=6 midlayer2_minwidth=6 midlayer2_maxwidth=6 midlayer2_prefwidth=6 midlayer3_minwidth=6 midlayer3_maxwidth=6 midlayer3_prefwidth=6 midlayer4_minwidth=6 midlayer4_maxwidth=6 midlayer4_prefwidth=6 bottomlayer_minwidth=6 bottomlayer_maxwidth=6.4 bottomlayer_prefwidth=6 maxuncoupledlength=1100
FabricationTestPointUsage TestPointUsage [All] p1: valid=2 allowmultiple=FALSE
FabricationTestpoint Testpoint [All] p1: side=3 testpointundercomponent=TRUE minsize=40 maxsize=100 preferedsize=60 minholesize=0 maxholesize=40 preferedholesize=32 testpointgrid=1 allowsidetop=TRUE allowsidebottom=TRUE usegrid=TRUE gridtolerance=0.01
FanoutControl Fanout_LCC [IsLCC] p1: bgadir=Out bgaviamode=Centered fanoutstyle=Auto fanoutdirection=Alternating viagrid=1 // Fanout_LCC (Default Rule)
FanoutControl Fanout_BGA [IsBGA] p2: bgadir=Out bgaviamode=Centered fanoutstyle=Auto fanoutdirection=Alternating viagrid=1 // Fanout_BGA (Default Rule)
FanoutControl Fanout_Default [All] p4: bgadir=Out bgaviamode=Centered fanoutstyle=Auto fanoutdirection=Alternating viagrid=1 // Fanout_Default (Default Rule)
FanoutControl Fanout_Small [(CompPinCount < 5)] p5: bgadir=Out bgaviamode=Centered fanoutstyle=Auto fanoutdirection=OutThenIn viagrid=1 // Fanout_Small (Default Rule)
HoleSize [All] p1: absolutevalues=TRUE maxlimit=260 minlimit=6 maxpercent=80.000 minpercent=20.000
Length [InNetClass('CON')] p1: maxlimit=2125 minlimit=2123
MatchedLengths [InDifferentialPairClass('HOST')] p1: tolerance=2 checknetsindiffpair=TRUE checkdiffpairvsdiffpair=FALSE checkxsignals=FALSE checkothers=FALSE
MinimumAnnularRing MinimumAnnularRing_ThermalPadVias [IsVia and InAnyComponent] p1: minimumring=3
MinimumAnnularRing [All] p2: minimumring=3
MinimumSolderMaskSliver MinimumSolderMaskSliver_Logo [InComponentClass('Logo') vs InComponentClass('Logo')] p1: minsoldermaskwidth=0.7
MinimumSolderMaskSliver [All] p2: minsoldermaskwidth=3.94
PlaneConnect [All] p1: planeconnectstyle=Direct reliefexpansion=10 reliefentries=4 reliefconductorwidth=10 reliefairgap=10
PolygonConnect [All] p1: connectstyle=Direct reliefconductorwidth=10 reliefentries=4 polygonreliefangle="90 Angle" airgapwidth=10
RoutingVias ThermalPadVias [IsVia and InAnyComponent] p1: holewidth=7.87 width=19.68 viastyle="Through Hole" minholewidth=7.87 minwidth=15 maxholewidth=12.99 maxwidth=23.62
RoutingVias [All] p2: holewidth=16 width=34 viastyle="Through Hole" minholewidth=6 minwidth=12 maxholewidth=40 maxwidth=65
SilkToBoardRegionClearance [Not ((IsComment or IsDesignator) And (Hide <> 'False')) and not InRegion(1000,500,4000,800)] p1:
SilkToSilkClearance SilkToSilkClearance_Pb-FreeLogo [(HasFootprint('Pb-Free_Overlay_Medium') OR HasFootprint('Pb-Free_Overlay_Small')) vs (HasFootprint('Pb-Free_Overlay_Medium') OR HasFootprint('Pb-Free_Overlay_Small'))] p1: silktosilkclearance=0
SilkToSilkClearance [All] p2: silktosilkclearance=3.94
SilkToSolderMaskClearance SilkToComponentPadClearance [(IsPad or IsFill or IsRegion) and InAnycomponent] p1: minsilkscreentomaskgap=5 clearancetoexposedcopper=TRUE
SilkToSolderMaskClearance "Silk to Solder Mask Opening" [All] p2: minsilkscreentomaskgap=3.94 clearancetoexposedcopper=FALSE
SolderMaskExpansion [All] p1: expansion=1.97 istentingtop=FALSE
UnRoutedNet [All] p1: checkbadconnections=TRUE
Width [All] p1: maxlimit=100 minlimit=6 preferedwidth=10 checkconnectedcopper=TRUE
14 further rules are at their usual default settings.

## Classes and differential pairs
differential pair class CON: con_RX1 con_RX2 con_RX3 con_RX4 con_RX5 con_RX6 con_RX8 con_RX17 CON_TX1 CON_TX2 CON_TX3 CON_TX4 CON_TX5 CON_TX6 CON_TX7 CON_TX8
net class CON: CON_RX1N CON_RX1P CON_RX2N CON_RX2P CON_RX3N CON_RX3P CON_RX4N CON_RX4P CON_RX5N CON_RX5P CON_RX6N CON_RX6P CON_RX7N CON_RX7P CON_RX8N CON_RX8P CON_TX1N CON_TX1P CON_TX2N CON_TX2P CON_TX3N CON_TX3P CON_TX4N CON_TX4P CON_TX5N CON_TX5P CON_TX6N CON_TX6P CON_TX7N CON_TX7P CON_TX8N CON_TX8P
differential pair class HOST: HOST_EGRESS_TX1 HOST_EGRESS_TX2 HOST_EGRESS_TX3 HOST_EGRESS_TX4 HOST_EGRESS_TX5 HOST_EGRESS_TX6 HOST_EGRESS_TX7 HOST_EGRESS_TX8 HOST_INGRESS_RX1 HOST_INGRESS_RX2 HOST_INGRESS_RX3 HOST_INGRESS_RX4 HOST_INGRESS_RX5 HOST_INGRESS_RX6 HOST_INGRESS_RX7 HOST_INGRESS_RX8
net class HOST: HOST_EGRESS_TX1N HOST_EGRESS_TX1P HOST_EGRESS_TX2N HOST_EGRESS_TX2P HOST_EGRESS_TX3N HOST_EGRESS_TX3P HOST_EGRESS_TX4N HOST_EGRESS_TX4P HOST_EGRESS_TX5N HOST_EGRESS_TX5P HOST_EGRESS_TX6N HOST_EGRESS_TX6P HOST_EGRESS_TX7N HOST_EGRESS_TX7P HOST_EGRESS_TX8N HOST_EGRESS_TX8P HOST_INGRESS_RX1N HOST_INGRESS_RX1P HOST_INGRESS_RX2N HOST_INGRESS_RX2P HOST_INGRESS_RX3N HOST_INGRESS_RX3P HOST_INGRESS_RX4N HOST_INGRESS_RX4P HOST_INGRESS_RX5N HOST_INGRESS_RX5P HOST_INGRESS_RX6N HOST_INGRESS_RX6P HOST_INGRESS_RX7N HOST_INGRESS_RX7P HOST_INGRESS_RX8N HOST_INGRESS_RX8P
component class DF410_Ingress_2: C62 C63 C64 C65 C66 C67 C68 C69 C70 C71 C72 J14 J15 J16 R64 R65 R66 R67 R68 R69 R70 R71 R72 R73 S2 U16
component class DF410_Egress_3: C73 C74 C75 C76 C77 C78 C79 C80 C81 C82 C83 J17 J18 J19 R74 R75 R76 R77 R78 R79 R80 R81 R82 R83 S3 U17
component class Shunt: SH-J1
component class QSFP-DD_Connector: C95 C96 D10 D11 D12 D13 D14 J23 J24 J25 J26 J27 J28 J45 R94 R95 R96 R97 R98 R99 R100 R101 R102 R103 TP3 TP4
component class FTDI_USB: C1 C2 C3 C4 C5 C6 C7 C8 C9 C10 C11 C12 C13 C14 C15 C16 C17 C18 C19 C20 C21 C22 J1 J2 L1 L2 L3 L4 L5 R1 R2 R3 R4 R5 R6 R7 R8 R9 R10 R11 R12 R13 TP1 TP2 U1 U2 U3 U4 U5 Y1
component class DF410_Ingress_1: C50 C51 C52 C53 C54 C55 C56 C57 C58 C59 C60 C61 J9 J10 J11 J12 J13 R52 R53 R54 R55 R56 R57 R58 R59 R60 R61 R62 R63 S1 U15 Y2
component class PWR_Supplies: C23 C24 C25 C26 C27 C28 C29 C30 C31 C32 C33 C34 C35 C36 C37 C38 C39 C40 C41 C42 C43 C44 C45 C46 C47 C48 C49 D1 D2 D3 D4 D5 D6 D7 D8 D9 F1 J3 J4 J5 J6 J7 J8 L6 L7 R14 R15 R16 R17 R18 R19 R20 R21 R22 R23 R24 R25 R26 R27 R28 R29 R30 R31 R32 R33 R34 R35 R36 R37 R38 R39 R40 R41 R42 R43 R44 R45 R46 R47 R48 R49 R50 R51 U6 U7 U8 U9 U10 U11 U12 U13 U14
component class DF410_Egress_4: C84 C85 C86 C87 C88 C89 C90 C91 C92 C93 C94 J20 J21 J22 R84 R85 R86 R87 R88 R89 R90 R91 R92 R93 S4 U18
component class Header: J1 J12 J24 J25 J26 J28 J45
component class "Mounting Holes": H1 H2 H3 H4
component class Hardware: FID1 FID2 FID3 FID4 FID5 FID6 H1 H2 H3 H4 LBL1 Logo1 Logo3 Logo4 SH-J1 ZZ1 ZZ2 ZZ3 ZZ4 ZZ5
component class FiducialMark: FID1 FID2 FID3 FID4 FID5 FID6
component class AssemblyNote: ZZ1 ZZ2 ZZ3 ZZ4 ZZ5
component class Label: LBL1
differential pair CON_TX8: +CON_TX8N -CON_TX8P
differential pair CON_TX7: +CON_TX7N -CON_TX7P
differential pair CON_TX6: +CON_TX6N -CON_TX6P
differential pair CON_TX5: +CON_TX5N -CON_TX5P
differential pair CON_TX4: +CON_TX4N -CON_TX4P
differential pair CON_TX3: +CON_TX3N -CON_TX3P
differential pair CON_TX2: +CON_TX2N -CON_TX2P
differential pair CON_TX1: +CON_TX1N -CON_TX1P
differential pair con_RX8: +CON_RX8N -CON_RX8P
differential pair con_RX17: +CON_RX7N -CON_RX7P
differential pair con_RX6: +CON_RX6N -CON_RX6P
differential pair con_RX5: +CON_RX5N -CON_RX5P
differential pair con_RX4: +CON_RX4N -CON_RX4P
differential pair con_RX3: +CON_RX3P -CON_RX3N
differential pair con_RX2: +CON_RX2N -CON_RX2P
differential pair con_RX1: +CON_RX1N -CON_RX1P
differential pair HOST_EGRESS_TX8: +HOST_EGRESS_TX8N -HOST_EGRESS_TX8P
differential pair HOST_EGRESS_TX7: +HOST_EGRESS_TX7N -HOST_EGRESS_TX7P
differential pair HOST_EGRESS_TX6: +HOST_EGRESS_TX6N -HOST_EGRESS_TX6P
differential pair HOST_EGRESS_TX5: +HOST_EGRESS_TX5N -HOST_EGRESS_TX5P
differential pair HOST_EGRESS_TX4: +HOST_EGRESS_TX4N -HOST_EGRESS_TX4P
differential pair HOST_EGRESS_TX3: +HOST_EGRESS_TX3N -HOST_EGRESS_TX3P
differential pair HOST_EGRESS_TX2: +HOST_EGRESS_TX2N -HOST_EGRESS_TX2P
differential pair HOST_EGRESS_TX1: +HOST_EGRESS_TX1N -HOST_EGRESS_TX1P
differential pair HOST_INGRESS_RX4: +HOST_INGRESS_RX4P -HOST_INGRESS_RX4N
differential pair HOST_INGRESS_RX2: +HOST_INGRESS_RX2P -HOST_INGRESS_RX2N
differential pair HOST_INGRESS_RX8: +HOST_INGRESS_RX8P -HOST_INGRESS_RX8N
differential pair HOST_INGRESS_RX6: +HOST_INGRESS_RX6P -HOST_INGRESS_RX6N
differential pair HOST_INGRESS_RX7: +HOST_INGRESS_RX7P -HOST_INGRESS_RX7N
differential pair HOST_INGRESS_RX5: +HOST_INGRESS_RX5P -HOST_INGRESS_RX5N
differential pair HOST_INGRESS_RX1: +HOST_INGRESS_RX1P -HOST_INGRESS_RX1N
differential pair HOST_INGRESS_RX3: +HOST_INGRESS_RX3P -HOST_INGRESS_RX3N

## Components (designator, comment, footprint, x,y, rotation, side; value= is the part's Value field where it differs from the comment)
C1 "C1005X5R1A475K050BC" 0402_065 304,1410.5 r90 top value=4.7uF
C2 "EMK105B7104KV-F" 0402 352.64,1410.5 r90 top value=0.1uF
C3 "C1005X5R1A475K050BC" 0402_065 343.13,1027.83 r0 top value=4.7uF
C4 "EMK105B7104KV-F" 0402 343.13,977.83 r0 top value=0.1uF
C5 "C1005X5R1A475K050BC" 0402_065 504.64,1410.5 r270 top value=4.7uF
C6 "EMK105B7104KV-F" 0402 455.56,1410.5 r270 top value=0.1uF
C7 "C1005X5R1A475K050BC" 0402_065 320.49,1114.13 r270 top value=4.7uF
C8 "EMK105B7104KV-F" 0402 369.57,1114.13 r270 top value=0.1uF
C9 "EMK105B7104KV-F" 0402 1246.32,1390.41 r90 top value=0.1uF
C10 "EMK105B7104KV-F" 0402 1256.47,1102.3 r180 top value=0.1uF
C11 "CL05A106MP8NUB8" 0402_090 571.78,600.18 r180 top value=10uF
C12 "C3216X5R1A107M160AC" 1206_190 522.56,659.23 r180 top value=100uF
C13 "EMK105B7104KV-F" 0402 648.53,1229.94 r0 top value=0.1uF
C14 "GRM1555C1H220JA01D" 0402 923.97,552.32 r270 bottom value=22pF
C15 "GRM1555C1H220JA01D" 0402 922.91,388.6 r90 bottom value=22pF
C16 "GRM155R61C103KA01D" 0402 671.71,157.08 r270 top value=0.01uF
C17 "EMK105B7104KV-F" 0402 621.89,287.98 r270 top value=0.1uF
C18 "C1005X5R1A475K050BC" 0402_065 563.43,287.98 r270 top value=4.7uF
C19 "EMK105B7104KV-F" 0402 125,775 r180 top value=0.1uF
C20 "EMK105B7104KV-F" 0402 125,775 r180 bottom value=0.1uF
C21 "GJM1555C1H270JB01" 0402 825.79,388.6 r270 bottom value=27pF
C22 "GJM1555C1H270JB01" 0402 630.23,519.47 r180 bottom value=27pF
C23 "EMK105BJ105KVHF" 0402 1314.21,4387.6 r0 top value=1uF
C24 "EMK105BJ105KVHF" 0402 1895,4392.5 r0 top value=1uF
C25 "EMK105BJ105KVHF" 0402 2400.63,4383.17 r0 top value=1uF
C26 "GRT31CR61A476KE13L" 1206_180 2042.12,4053.39 r90 top value=47uF
C27 "C3216X5R1A107M160AC" 1206_190 2042.12,4053.39 r90 bottom value=100uF
C28 "GRM155R60J226ME11D" 0402 1851.77,4029.43 r90 bottom value=22uF
C29 "GRM155R60J226ME11D" 0402 1912,4030.39 r90 top value=22uF
C30 "CL05A106MP8NUB8" 0402_090 1912,4030.39 r90 bottom value=10uF
C31 "GRM31CR60G227ME11L" 1206_190 1374.18,3942.85 r270 top value=220uF
C32 "CL05A106MP8NUB8" 0402_090 1524.32,3742.44 r90 top value=10uF
C33 "CL05A106MP8NUB8" 0402_090 1557.32,3742.44 r90 top value=10uF
C34 "GRM155R60J226ME11D" 0402 1662.37,3194.52 r180 bottom value=22uF
C35 "GRM155R60J226ME11D" 0402 1661.99,3255.52 r180 bottom value=22uF
C36 "CL05A106MP8NUB8" 0402_090 2081.14,3706.72 r90 bottom value=10uF
C37 "CL05A106MP8NUB8" 0402_090 2041.41,3706.06 r90 bottom value=10uF
C38 "GRM155R60J226ME11D" 0402 2211.98,3316.7 r180 bottom value=22uF
C39 "GRM155R60J226ME11D" 0402 2212.6,3158.4 r180 top value=22uF
C40 "CL05A106MP8NUB8" 0402_090 259.12,3378.59 r90 bottom value=10uF
C41 "CL05A106MP8NUB8" 0402_090 440.21,3656.78 r0 bottom value=10uF
C42 "EMK105BJ105KVHF" 0402 440.25,3552.6 r0 bottom value=1uF
C43 "GRM155R71E104KE14D" 0402 439.92,3606.6 r0 bottom value=0.1uF
C44 "GRM155R71E104KE14D" 0402 85.59,3478.86 r180 top value=0.1uF
C45 "CL05A106MP8NUB8" 0402_090 824.97,3358.06 r90 bottom value=10uF
C46 "CL05A106MP8NUB8" 0402_090 1007.87,3653.82 r0 bottom value=10uF
C47 "EMK105BJ105KVHF" 0402 1007.59,3603.05 r0 bottom value=1uF
C48 "GRM155R71E104KE14D" 0402 1007.59,3549.36 r0 bottom value=0.1uF
C49 "GRM155R71E104KE14D" 0402 654.83,3475.62 r180 top value=0.1uF
C50 "GRM033C71C104KE14D" 0201_033#1 2932.51,2243.26 r180 bottom value=0.1uF
C51 "GRM033C71C104KE14D" 0201_033#1 2964.01,2274.76 r180 bottom value=0.1uF
C52 "GRM033C71C104KE14D" 0201_033#1 3021.49,2243.26 r0 bottom value=0.1uF
C53 "EMK105B7104KV-F" 0402 2186.4,687 r0 bottom value=0.1uF
C54 "GRM033R61E103KA12D" 0201_033#1 3021.49,2180.27 r0 bottom value=0.01uF
C55 "CL05B224KO5NNNC" 0402 3183.3,2428.59 r90 bottom value=0.22uF
C56 "GRM033C71C104KE14D" 0201_033#1 2964.01,2148.77 r180 bottom value=0.1uF
C57 "GRM188R61C105KA93D" 0603 3302.29,2439.28 r90 bottom value=1uF
C58 "GRM188R61C105KA93D" 0603 3240.29,2439.28 r90 bottom value=1uF
C59 "GRM033R61E103KA12D" 0201_033#1 2932.18,2181.31 r180 bottom value=0.01uF
C60 "GRM033C71C104KE14D" 0201_033#2 3054.8,2210.3 r0 bottom value=0.1uF
C61 "GRM188R61C105KA93D" 0603 3037.34,1966 r180 bottom value=1uF
C62 "GRM033C71C104KE14D" 0201_033#1 2964.01,1694.64 r180 bottom value=0.1uF
C63 "GRM033C71C104KE14D" 0201_033#1 2965.01,1535.5 r180 bottom value=0.1uF
C64 "GRM033C71C104KE14D" 0201_033#1 2932.51,1573.4 r180 bottom value=0.1uF
C65 "GRM033R61E103KA12D" 0201_033#1 3021.49,1663.14 r0 bottom value=0.01uF
C66 "CL05B224KO5NNNC" 0402 2756,1986.4 r180 bottom value=0.22uF
C67 "GRM033C71C104KE14D" 0201_033#1 3021.61,1575.22 r0 bottom value=0.1uF
C68 "GRM188R61C105KA93D" 0603 2744.4,1929.4 r180 bottom value=1uF
C69 "GRM188R61C105KA93D" 0603 2744.4,1867.4 r180 bottom value=1uF
C70 "GRM033R61E103KA12D" 0201_033#1 2932.51,1663.14 r180 bottom value=0.01uF
C71 "GRM033C71C104KE14D" 0201_033#2 3041.49,1622.39 r0 bottom value=0.1uF
C72 "GRM188R61C105KA93D" 0603 2876.5,1692 r90 bottom value=1uF
C73 "GRM033C71C104KE14D" 0201_033#1 2964.01,2854.87 r180 bottom value=0.1uF
C74 "GRM033C71C104KE14D" 0201_033#1 2932.51,2823.38 r180 bottom value=0.1uF
C75 "GRM033C71C104KE14D" 0201_033#2 3021.49,2728.89 r0 bottom value=0.1uF
C76 "GRM033R61E103KA12D" 0201_033#1 3021.49,2823.38 r0 bottom value=0.01uF
C77 "CL05B224KO5NNNC" 0402 3169.9,2907.41 r270 bottom value=0.22uF
C78 "GRM033C71C104KE14D" 0201_033#1 2932.18,2761.43 r180 bottom value=0.1uF
C79 "GRM188R61C105KA93D" 0603 3288.9,2895.82 r270 bottom value=1uF
C80 "GRM188R61C105KA93D" 0603 3226.9,2895.82 r270 bottom value=1uF
C81 "GRM033R61E103KA12D" 0201_033#1 3021.55,2755.11 r0 bottom value=0.01uF
C82 "GRM033C71C104KE14D" 0201_033#2 3041.49,2782.8 r0 bottom value=0.1uF
C83 "GRM188R61C105KA93D" 0603 2872,2814.3 r90 bottom value=1uF
C84 "GRM033C71C104KE14D" 0201_033#1 2964.01,3434.99 r180 bottom value=0.1uF
C85 "GRM033C71C104KE14D" 0201_033#1 3021.2,3311.4 r0 bottom value=0.1uF
C86 "GRM033C71C104KE14D" 0201_033#1 2932.18,3341.55 r180 bottom value=0.1uF
C87 "GRM033R61E103KA12D" 0201_033#1 3021.09,3288.53 r0 bottom value=0.01uF
C88 "CL05B224KO5NNNC" 0402 3230.19,3554.52 r0 bottom value=0.22uF
C89 "GRM033C71C104KE14D" 0201_033#1 2932.51,3403.5 r180 bottom value=0.1uF
C90 "GRM188R61C105KA93D" 0603 3241.78,3673.52 r0 bottom value=1uF
C91 "GRM188R61C105KA93D" 0603 3241.78,3611.52 r0 bottom value=1uF
C92 "GRM033R61E103KA12D" 0201_033#1 3021.49,3403.5 r0 bottom value=0.01uF
C93 "GRM033C71C104KE14D" 0201_033#2 3038.8,3368.39 r90 bottom value=0.1uF
C94 "GRM188R61C105KA93D" 0603 3078.8,3317 r270 bottom value=1uF
C95 "GRM21BR61C106KE15K" 0805_HV 1697.1,1201.14 r90 top value=10uF
C96 "GRM185R61C105KE44D" 0603 1698.09,1202.14 r90 bottom value=1uF
D1 "LTST-C150KGKT" LTST-C150_1206_Green 1853.12,4225.99 r270 top value=Green
D2 "LTST-C150KGKT" LTST-C150_1206_Green 1445.99,3255.52 r0 top value=Green
D3 "LTST-C150KGKT" LTST-C150_1206_Green 1995,3205.9 r0 top value=Green
D4 "LTST-C150KGKT" LTST-C150_1206_Green 607.3,4359.68 r270 top value=Green
D5 "LTST-C150KGKT" LTST-C150_1206_Green 761.3,4184.27 r180 top value=Green
D6 "LTST-C150KGKT" LTST-C150_1206_Green 761.3,4080.5 r180 top value=Green
D7 "LTST-C150KGKT" LTST-C150_1206_Green 607.3,3902.68 r90 top value=Green
D8 "LTST-C150KGKT" LTST-C150_1206_Green 462.4,3409.29 r90 top value=Green
D9 "LTST-C150KGKT" LTST-C150_1206_Green 1031.21,3411.36 r90 top value=Green
D10 "LG M67K-G1J2-24-Z" LG_M67K_Green 1794.09,1700.87 r270 top value=Green
D11 "LG M67K-G1J2-24-Z" LG_M67K_Green 1899.09,1700.87 r270 top value=Green
D12 "LG M67K-G1J2-24-Z" LG_M67K_Green 2004.09,1700.87 r270 top value=Green
D13 "LG M67K-G1J2-24-Z" LG_M67K_Green 2109.09,1700.87 r270 top value=Green
D14 "LG M67K-G1J2-24-Z" LG_M67K_Green 2219.09,1700.87 r270 top value=Green
F1 "0440008.WR" 1206 2130.12,4057.89 r90 top
FID1 "Fiducial" Fiducial10-30 640,4700 r0 top locked
FID2 "Fiducial" Fiducial10-30 360.22,335 r0 top
FID3 "Fiducial" Fiducial10-30 5250,4480 r0 top locked
FID4 "Fiducial" Fiducial10-30 575,4648 r180 bottom locked
FID5 "Fiducial" Fiducial10-30 417,177 r180 bottom locked
FID6 "Fiducial" Fiducial10-30 5105,4309.96 r180 bottom locked
H1 "NY PMS 440 0025 PH" "NY PMS 440 0025 PH" 100,200 r0 top locked
H2 "NY PMS 440 0025 PH" "NY PMS 440 0025 PH" 5200,200 r0 top locked
H3 "NY PMS 440 0025 PH" "NY PMS 440 0025 PH" 100,4800 r180 bottom locked
H4 "NY PMS 440 0025 PH" "NY PMS 440 0025 PH" 5200,4800 r180 bottom locked
J1 "HTSW-103-07-G-S" Samtec_HTSW-103-07-G-S 1328,801.13 r90 top
J2 "0565790576" Molex_0565790576 954.13,2.27 r0 top
J3 "RAPC712X" CONN_RAPC712X 1216,5000 r90 top
J4 "RAPC712X" CONN_RAPC712X 1729,5002 r90 top
J5 "RAPC712X" CONN_RAPC712X 2240,5000 r90 top
J6 "HTSW-102-09-G-S" Samtec_HTSW-102-09-x-S 1705.92,4054.43 r90 top
J7 "HTSW-102-09-G-S" Samtec_HTSW-102-09-x-S 1192.73,4060.45 r90 top
J8 "HTSW-102-09-G-S" Samtec_HTSW-102-09-x-S 1509.07,4055.17 r90 top
J9 "73252-0161" FP-73252-0161_CONN_RF_JACK-MFG#1 5034.89,2292.33 r270 top
J10 "73252-0161" FP-73252-0161_CONN_RF_JACK-MFG#1 5031.16,2019.47 r90 top
J11 "1X8A_81_MXP-S50-0-2/111_NE" H+S_1X8A_81_MXP-S50-0-2_111N 4486.77,1467.19 r270 top
J12 "PBC02DAAN" Sullins_PxC02DAAN 2411.39,535.3 r0 top
J13 "SMA-J-P-H-ST-TH1" SAMTEC_SMA-J-P-H-ST-TH1 2424.45,150.93 r0 top
J14 "73252-0161" FP-73252-0161_CONN_RF_JACK-MFG#2 4018.22,1207.94 r225 top
J15 "73252-0161" FP-73252-0161_CONN_RF_JACK-MFG#2 3827.91,1012.36 r45 top
J16 "1X8A_81_MXP-S50-0-2/111_NE" H+S_1X8A_81_MXP-S50-0-2_111N 3438.1,484.47 r180 top
J17 "73252-0161" FP-73252-0161_CONN_RF_JACK-MFG#2 5031.15,2984.18 r270 top
J18 "73252-0161" FP-73252-0161_CONN_RF_JACK-MFG#2 5034.89,2711.31 r90 top
J19 "1X8A_81_MXP-S50-0-2/111_NE" H+S_1X8A_81_MXP-S50-0-2_111N 4486.77,3536.45 r270 top
J20 "73252-0161" FP-73252-0161_CONN_RF_JACK-MFG#2 3827.91,3991.29 r315 top
J21 "73252-0161" FP-73252-0161_CONN_RF_JACK-MFG#2 4018.22,3795.71 r135 top
J22 "1X8A_81_MXP-S50-0-2/111_NE" H+S_1X8A_81_MXP-S50-0-2_111N 3438.1,4519.18 r0 top
J23 "2027180100" FP-2027180100_HDR76-MFG 1839.17,2486 r0 top locked
J24 "TSW-103-08-G-S" Samtec_TSW-103-08-x-S 1744.46,572.95 r270 top
J25 "PBC02DAAN" Sullins_PxC02DAAN 1933.42,601.96 r0 top
J26 "TSW-105-08-G-D" SAMTEC_TSW-105-08-X-D 2003.16,1402.15 r90 top
J27 "2031431350" FP-2031431350_CAGE_QSFP-DD-MFG 1000,2486 r90 top locked
J28 "TSW-106-07-G-D" TSW-106-07-G-D 2014.72,866.12 r0 top
L1 "BLM15AX601SN1D" 0402 405.64,1410.5 r90 top value="600 ohm"
L2 "BLM15AX601SN1D" 0402 243.42,1409.13 r90 top value="600 ohm"
L3 "742792641" 0603 844.91,393.67 r270 top value="300 ohm"
L4 "742792641" 0603 943.66,395.6 r270 top value="300 ohm"
L5 "742792622" 0603 677.14,275.99 r90 top value="180 ohm"
L6 "744373210022" 744373210022 1641.37,3419.52 r0 top value=220nH
L7 "744373210022" 744373210022 2185.63,3391.95 r0 top value=220nH
LBL1 "THT-14-423-10" Label_650x200 5161.79,1450.48 r90 top
Logo1 "CE Mark" CE_Mark_5mm 1605.4,164.8 r0 top
Logo3 "FCC disclaimer" FCC_disclaimer 3477.75,71.15 r0 top
Logo4 "WEEE logo" WEEE_Minimum 1927.6,239.43 r0 top
R1 "ERJ-2RKF2001X" 0402 1473,637.13 r180 top value=2.00k
R2 "CRCW04022R49FKED" 0402 1473,692.13 r180 top value=2.49
R3 "ERJ-2RKF2001X" 0402 1473,747.13 r180 top value=2.00k
R4 "CRCW04022R49FKED" 0402 1473,857.13 r0 top value=2.49
R5 "CRCW04022R49FKED" 0402 1473,802.13 r180 top value=2.49
R6 "CRCW040212K1FKED" 0402 874.4,388.6 r90 bottom value=12.1k
R7 "ERJ-2RKF4701X" 0402 504.38,287.98 r270 top value=4.70k
R8 "CRCW04021K00FKED" 0402 1042.08,413.6 r90 top value=1.00k
R9 "PCF0402-12-10K0BT1" 0402 1097.98,413.6 r270 top value=10.0k
R10 "PCF0402-12-10K0BT1" 0402 569.9,803.24 r0 top value=10.0k
R11 "PCF0402-12-10K0BT1" 0402 569.9,854.43 r0 top value=10.0k
R12 "PCF0402-12-10K0BT1" 0402 569.9,749.39 r0 top value=10.0k
R13 "ERA2AEB222X" 0402 569.9,906 r180 top value=2.20k
R14 "RC0201FR-074R7L" 0201 1276.73,4011.39 r0 top value=4.70
R15 "MCR01MZPF1001" 0402 1851.77,4029.43 r270 top value=1.00k
R16 "ERJ-2GE0R00X" 0402 1661.99,3255.52 r180 top value=0
R17 "MCR01MZPF1001" 0402 1662.37,3194.52 r0 top value=1.00k
R18 "CRCW040210K0JNED" 0402 1417.2,3622.3 r90 top value=10k
R19 "CRCW040210K0JNED" 0402 1390.87,3526.82 r0 top value=10k
R20 "ERJ-2GE0R00X" 0402 1941.76,3687.1 r0 top value=0
R21 "ERJ-2GE0R00X" 0402 1940.89,3632.35 r0 top value=0
R22 "ERJ-2GE0R00X" 0402 2211.91,3266.45 r180 bottom value=0
R23 "MCR01MZPF1001" 0402 2212.6,3206.2 r0 top value=1.00k
R24 "CRCW040210K0JNED" 0402 1940.89,3575.36 r180 top value=10k
R25 "CRCW040210K0JNED" 0402 1941.16,3509.56 r0 top value=10k
R26 "ERJ-2GE0R00X" 0402 684.55,3363.26 r90 top value=0
R27 "CRCW040215R0FKED" 0402 79.3,4182.86 r0 top value=15.0
R28 "CRCW0402261RFKED" 0402 583.68,4214.95 r0 top value=261
R29 "CRCW040215R0FKED" 0402 79.3,4131.59 r0 top value=15.0
R30 "CRCW0402261RFKED" 0402 583.68,4163.77 r0 top value=261
R31 "ERJ-2GE0R00X" 0402 769.4,3358.32 r90 top value=0
R32 "CRCW040215R0FKED" 0402 79.3,4076.59 r0 top value=15.0
R33 "CRCW0402261RFKED" 0402 583.68,4106.27 r0 top value=261
R34 "CRCW040215R0FKED" 0402 79.3,4024.4 r0 top value=15.0
R35 "CRCW0402261RFKED" 0402 583.68,4054.91 r0 top value=261
R36 "ERJ-2GE0R00X" 0402 440.25,3657.06 r0 top value=0
R37 "ERJ-2GE0R00X" 0402 184.11,3616.91 r270 top value=0
R38 "RC0402FR-071K87L" 0402 564.88,3608.72 r180 top value=1.87k
R39 "CRCW04022R49FKED" 0402 439.97,3606.29 r180 top value=2.49
R40 "CRCW040244K2FKED" 0402 314.48,3377.97 r270 top value=44.2k
R41 "MCR01MZPF1001" 0402 439.97,3552.6 r180 top value=1.00k
R42 "CRCW04021K50FKED" 0402 331,3499.36 r180 top value=1.50k
R43 "CRCW04022R49FKED" 0402 564.59,3667.48 r180 top value=2.49
R44 "ERJ-2GE0R00X" 0402 1007.87,3653.82 r0 top value=0
R45 "ERJ-2GE0R00X" 0402 751.73,3613.67 r270 top value=0
R46 "RC0402FR-071K87L" 0402 1132.5,3605.49 r180 top value=1.87k
R47 "CRCW04022R49FKED" 0402 1007.59,3603.05 r180 top value=2.49
R48 "CRCW040244K2FKED" 0402 824.97,3358.06 r270 top value=44.2k
R49 "MCR01MZPF1001" 0402 1007.59,3549.36 r180 top value=1.00k
R50 "CRCW04021K50FKED" 0402 922.71,3495.54 r180 top value=1.50k
R51 "CRCW04022R49FKED" 0402 1132.21,3664.24 r180 top value=2.49
R52 "CRCW04021K00FKED" 0402 3065.5,2432.39 r90 top value=1.00k
R53 "CRCW04021K00FKED" 0402 3008,2432.39 r90 top value=1.00k
R54 "CRCW04021K00FKED" 0402 3044.24,2021.58 r0 bottom value=1.00k
R55 "CRCW04021K00FKED" 0402 2953.46,2431.01 r90 top value=1.00k
R56 "ERJ-2GE0R00X" 0402 2900.93,2429.64 r90 top value=0
R57 "CRCW040210R2FKED" 0402 2351.92,1057.49 r90 top value=10.2
R58 "CRCW04024K70JNED" 0402 2095.29,604.35 r90 top value=4.7k
R59 "ERJ-2GE0R00X" 0402 2585.33,1055.53 r270 top value=0
R60 "Resistor" 0402 2269.29,602.35 r90 top value=33
R61 "ERJ-2RKF2001X" 0402 1140.1,1390.41 r90 top value=2.00k
R62 "ERJ-2GE0R00X" 0402 1190.55,1390.41 r270 top value=0
R63 "ERJ-2GE0R00X" 0402 2928.1,2021.58 r180 bottom value=0
R64 "CRCW04021K00FKED" 0402 3019.76,1405.89 r270 top value=1.00k
R65 "CRCW04021K00FKED" 0402 3073.97,1819.74 r0 top value=1.00k
R66 "CRCW04021K00FKED" 0402 2962.95,1405.83 r270 top value=1.00k
R67 "CRCW04021K00FKED" 0402 2950.34,1858.12 r180 top value=1.00k
R68 "ERJ-2GE0R00X" 0402 1083.06,1390.41 r270 top value=0
R69 "CRCW040210R2FKED" 0402 2583.32,1394.18 r270 top value=10.2
R70 "ERJ-2GE0R00X" 0402 2349.3,1401.99 r270 top value=0
R71 "ERJ-2RKF2001X" 0402 1032.4,1390.41 r90 top value=2.00k
R72 "ERJ-2GE0R00X" 0402 979.78,1390.41 r270 top value=0
R73 "ERJ-2GE0R00X" 0402 2875.47,1409.25 r180 top value=0
R74 "CRCW04021K00FKED" 0402 2945.39,3054.94 r90 top value=1.00k
R75 "CRCW04021K00FKED" 0402 2945.18,2567.72 r270 top value=1.00k
R76 "CRCW04021K00FKED" 0402 914.21,3818.33 r270 top value=1.00k
R77 "CRCW04021K00FKED" 0402 975.5,3818 r270 top value=1.00k
R78 "ERJ-2GE0R00X" 0402 922.91,1390.41 r270 top value=0
R79 "CRCW040210R2FKED" 0402 2589.04,3461.11 r270 top value=10.2
R80 "ERJ-2GE0R00X" 0402 2377.07,3463.07 r270 top value=0
R81 "ERJ-2RKF2001X" 0402 874.4,1390.41 r90 bottom value=2.00k
R82 "ERJ-2GE0R00X" 0402 874.4,1390.41 r270 top value=0
R83 "ERJ-2GE0R00X" 0402 3000.52,3054.8 r90 top value=0
R84 "CRCW04021K00FKED" 0402 2839,3631.9 r90 top value=1.00k
R85 "CRCW04021K00FKED" 0402 2945.5,3163.38 r270 bottom value=1.00k
R86 "CRCW04021K00FKED" 0402 1185.47,3807.39 r270 top value=1.00k
R87 "CRCW04021K00FKED" 0402 1129.37,3807.39 r270 top value=1.00k
R88 "ERJ-2GE0R00X" 0402 819.9,1391 r270 bottom value=0
R89 "CRCW040210R2FKED" 0402 2608.12,3687.24 r270 top value=10.2
R90 "ERJ-2GE0R00X" 0402 2393.85,3689.19 r270 top value=0
R91 "ERJ-2RKF2001X" 0402 759.52,1390.41 r90 top value=2.00k
R92 "ERJ-2GE0R00X" 0402 2918.4,3561.25 r180 top value=0
R93 "ERJ-2GE0R00X" 0402 704.1,1390.41 r270 top value=0
R94 "CRCW04024K70JNED" 0402 1903.16,1188.86 r270 top value=4.7k
R95 "CRCW04024K70JNED" 0402 2203.16,1188.86 r270 top value=4.7k
R96 "CRCW04024K70JNED" 0402 1803.16,1188.86 r270 top value=4.7k
R97 "CRCW04024K70JNED" 0402 2003.16,1188.86 r270 top value=4.7k
R98 "CRCW04024K70JNED" 0402 2103.16,1188.86 r270 top value=4.7k
R99 "CRCW0603200RFKEA" 0603 1794.09,1708.74 r90 bottom value=200
R100 "CRCW0603200RFKEA" 0603 1899.09,1708.74 r90 bottom value=200
R101 "CRCW0603200RFKEA" 0603 2004.09,1708.74 r90 bottom value=200
R102 "CRCW0603200RFKEA" 0603 2109.09,1708.74 r90 bottom value=200
R103 "CRCW0603200RFKEA" 0603 2219.09,1708.74 r90 bottom value=200
S1 "KMR211GLFS" SW_KMR211GLFS 2467.26,1108.67 r270 top
S2 "KMR211GLFS" SW_KMR211GLFS 2470.23,1348.86 r90 top
S3 "KMR211GLFS" SW_KMR211GLFS 2482.14,3409.93 r90 top
S4 "KMR211GLFS" SW_KMR211GLFS 2495.21,3636.06 r90 top
SH-J1 "SPC02SYAN" SPC02SYAN 2366.26,538.89 r90 top value=1x2
TP1 "5015" Testpoint_Keystone_Miniature 332.14,639.55 r270 top
TP2 "5015" Testpoint_Keystone_Miniature 1334,1209.2 r0 top
TP3 "5015" Testpoint_Keystone_Miniature 1579,1206 r90 top
TP4 "5015" Testpoint_Keystone_Miniature 135,3101 r0 top
U1 "TLV70233DBVR" DBV0005A_N 340.53,1263.34 r90 top
U2 "TXB0108RGYR" RGY0020A 1082.45,1194.65 r270 top
U3 "FT4232HL-REEL" FP-FT4232HL-REEL_LQFP64-MFG 933.82,747.81 r90 top
U4 "TXB0108RGYR" RGY0020A 831.01,1199.43 r270 top
U5 "93LC46B-I/ST" TSSOP-8 342.64,816.04 r180 top
U6 "TPS62867RQY" RQY0009A-MFG 1547.63,3625.22 r270 top
U7 "NFM31PC276B0J3L" Murata_NFM31P 1714.85,3642.39 r90 top value="27 uF"
U8 "TPS62867RQY" RQY0009A-MFG 2091.88,3597.65 r270 top
U9 "NFM31PC276B0J3L" Murata_NFM31P 2259.11,3614.82 r90 top value="27 uF"
U10 "SN74AVC4T245PWR" PW0016A_N 333.25,4144.47 r0 top
U11 "TPS7A5201RPST" RPS0012A 219.54,3498.54 r0 top
U12 "NFM31PC276B0J3L" Murata_NFM31P 332.7,3632.7 r90 top value="27 uF"
U13 "TPS7A5201RPST" RPS0012A 787.16,3495.3 r0 top
U14 "NFM31PC276B0J3L" Murata_NFM31P 900.59,3624.36 r90 top value="27 uF"
U15 "DS560DF410AMN" AMN0081A-MFG 2977,2211.76 r90 top locked
U16 "DS560DF410AMN" AMN0081A-MFG 2977,1631.65 r90 top locked
U17 "DS560DF410AMN" AMN0081A-MFG 2977,2791.88 r270 top locked
U18 "DS560DF410AMN" AMN0081A-MFG 2977,3372 r270 top locked
Y1 "ABMM2-12.000MHZ-E2-T" Abracon_ABMM2 571.78,472.22 r270 top
Y2 "ECS-1618-250-BN-TR" ECS-1618-250-BN-TR 2185.08,612.82 r0 top
ZZ1 "This Assembly Note is for PCB labels only" AssemblyNoteLabel 296.3,11432 r0 top
ZZ2 "These assemblies are ESD sensitive, ESD precautions shall be observed." AssemblyNote 296.3,11337 r0 top
ZZ3 "These assemblies must be clean and free from flux and all contaminants. Use of no clean flux is not acceptable." AssemblyNote 296.3,11232 r0 top
ZZ4 "These assemblies must comply with workmanship standards IPC-A-610 Class 2, unless otherwise specified." AssemblyNote 296.3,11122 r0 top
ZZ5 "These assemblies must comply with workmanship standards IPC-A-610 Class 2, unless otherwise specified." AssemblyNote 301.3,11012 r0 top

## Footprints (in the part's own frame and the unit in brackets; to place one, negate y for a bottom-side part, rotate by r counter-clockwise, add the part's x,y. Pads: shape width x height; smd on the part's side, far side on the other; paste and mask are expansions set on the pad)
0201 [mm] "Data from Kemet datasheet CC101_COM dated 7/28/11"
  rect 0.46x0.42 smd: 1(-0.33,0) 2(0.33,0)
  body extent -0.31,-0.16 0.31,0.16, height 0.26
0201_033#1 [mm] "SMD, 2-Leads, Height 0.33mm"
  rect 0.46x0.42 smd: 1(-0.33,0) 2(0.33,0)
  body extent -0.31,-0.16 0.31,0.16, height 0.33
0201_033#2 [mm] "SMD, 2-Leads, Height 0.33mm"
  rect 0.46x0.42 smd mask+0.048: 1(-0.33,0) 2(0.33,0)
  silkscreen extent -0.75,-0.4 0.75,0.4, body extent -0.31,-0.16 0.31,0.16, height 0.33
0402 [mm] "0402 from SM-752 data"
  rect 0.8x0.6 smd: 1(-0.6,0) 2(0.6,0)
  silkscreen extent -1.22,-0.52 1.22,0.52, body extent -0.55,-0.3 0.55,0.3, height 0.6
0402_065 [mm] "0402"
  rect 0.8x0.6 smd: 1(-0.6,0) 2(0.6,0)
  silkscreen extent -1.22,-0.52 1.22,0.52, body extent -0.55,-0.3 0.55,0.3, height 0.65
0402_090 [mm] "SMD, 2-Leads, Body 1x0.5mm"
  rect 0.8x0.6 smd: 1(-0.6,0) 2(0.6,0)
  body extent -0.6,-0.35 0.6,0.35, height 0.9
0603 [mm] "0603 from SM-752 data"
  rect 1x0.95 smd: 1(-0.8,0) 2(0.8,0)
  silkscreen extent -1.52,-0.69 1.52,0.69, body extent -0.87,-0.47 0.87,0.47, height 1
0805_HV [mm] "0805 with 30mil clearance between pads"
  rect 0.8x1.4 smd: 1(-1.016,0) 2(1.016,0)
  silkscreen extent -1.88,-1.02 1.88,1.02, body extent -1.1,-0.72 1.1,0.72, height 1.45
1206 [mm] "1206 from SM-752 data"
  rect 1.3x1.85 smd: 1(-1.45,0) 2(1.45,0)
  silkscreen extent -2.4,-1.21 2.4,1.21, body extent -1.7,-0.9 1.7,0.9, height 1.35
1206_180 [mm] "1206_180"
  rect 1.1x1.6 smd: 1(-1.7,0) 2(1.7,0)
  silkscreen extent -0.9,-1 0.9,1, body extent -1.75,-0.95 1.75,0.95, height 1.8
1206_190 [mm] "1206_190"
  rect 1.1x1.6 smd: 1(-1.7,0) 2(1.7,0)
  silkscreen extent -0.9,-1 0.9,1, body extent -1.75,-0.95 1.75,0.95, height 1.9
744373210022 [mm]
  rect 1.5x2.3 smd mask+0.038: 1(-1.85,0) 2(1.85,0)
  silkscreen extent -2.41,-2.41 2.41,2.41, body extent -2.15,-2.15 2.15,2.15, height 1.2
Abracon_ABMM2 [mm] "SMD, 4-Leads, Body 6x3.6mm"
  rrect7% 1.4x1.8 smd: 1(-1.2,2.2) 2(-1.2,-2.2) 3(1.2,-2.2) 4(1.2,2.2)
  body extent -1.95,-3.1 1.95,3.1, height 1.2
AMN0081A-MFG [mm]
  round 0.4 smd: A1(-3.2,3.2) A2(-2.4,3.2) A3(-1.6,3.2) A4(-0.8,3.2) A5(0,3.2) A6(0.8,3.2) A7(1.6,3.2) A8(2.4,3.2) A9(3.2,3.2) B1(-3.2,2.4) B2(-2.4,2.4) B3(-1.6,2.4) B4(-0.8,2.4) B5(0,2.4) B6(0.8,2.4) B7(1.6,2.4) B8(2.4,2.4) B9(3.2,2.4) C1(-3.2,1.6) C2(-2.4,1.6) C3(-1.6,1.6) C4(-0.8,1.6) C5(0,1.6) C6(0.8,1.6) C7(1.6,1.6) C8(2.4,1.6) C9(3.2,1.6) D1(-3.2,0.8) D2(-2.4,0.8) D3(-1.6,0.8) D4(-0.8,0.8) D5(0,0.8) D6(0.8,0.8) D7(1.6,0.8) D8(2.4,0.8) D9(3.2,0.8) E1(-3.2,0) E2(-2.4,0) E3(-1.6,0) E4(-0.8,0) E5(0,0) E6(0.8,0) E7(1.6,0) E8(2.4,0) E9(3.2,0) F1(-3.2,-0.8) F2(-2.4,-0.8) F3(-1.6,-0.8) F4(-0.8,-0.8) F5(0,-0.8) F6(0.8,-0.8) F7(1.6,-0.8) F8(2.4,-0.8) F9(3.2,-0.8) G1(-3.2,-1.6) G2(-2.4,-1.6) G3(-1.6,-1.6) G4(-0.8,-1.6) G5(0,-1.6) G6(0.8,-1.6) G7(1.6,-1.6) G8(2.4,-1.6) G9(3.2,-1.6) H1(-3.2,-2.4) H2(-2.4,-2.4) H3(-1.6,-2.4) H4(-0.8,-2.4) H5(0,-2.4) H6(0.8,-2.4) H7(1.6,-2.4) H8(2.4,-2.4) H9(3.2,-2.4) J1(-3.2,-3.2) J2(-2.4,-3.2) J3(-1.6,-3.2) J4(-0.8,-3.2) J5(0,-3.2) J6(0.8,-3.2) J7(1.6,-3.2) J8(2.4,-3.2) J9(3.2,-3.2)
  silkscreen extent -4.75,-3.88 3.88,3.88, body extent -4.37,-4.38 4.38,4.38, height 0.25
AssemblyNote [mil] "Assembly Note"
AssemblyNoteLabel [mil] "Assembly Note for PCB Labels"
CE_Mark_5mm [mil] "Minimum text height for CE Mark"
  silkscreen extent -138,-98 138,98
CONN_RAPC712X [mm] "Conn_DC Jack"
  oval 1.7x4.3 hole 1.01 slot 3.56 at 90 deg: 1(-13.741,0)
  oval 1.5x3.8 hole 0.76 slot 3.05 at 90 deg: 2(-7.493,0)
  oval 3.8x1.5 hole 0.76 slot 3.05 at 0 deg: 3(-10.744,4.7)
  silkscreen extent -14.48,-4.57 0.25,4.57, body extent -14.5,-4.57 0.23,4.83, height 11.18
DBV0005A_N [mm] "SOT23, 5-Leads, Body 2.9x1.6mm, Pitch 0.95mm, Lead Span 2.8mm, IPC Medium Density"
  rrect17% 1x0.6 smd: 1(-1.375,0.95) 2(-1.375,0) 3(-1.375,-0.95) 4(1.375,-0.95) 5(1.375,0.95)
  silkscreen extent -0.25,-1.55 0.25,1.55, body extent -1.42,-1.46 1.42,1.46, height 1.09
ECS-1618-250-BN-TR [mm]
  rect 0.6x0.5 smd mask+0.038: 1(-0.55,-0.4) 2(0.55,-0.4) 3(0.55,0.4) 4(-0.55,0.4)
  silkscreen extent -1.52,-0.9 1.1,0.9, body extent -0.8,-0.6 0.8,0.6, height 0.69
FCC_disclaimer [mil]
Fiducial10-30 [mm]
  round 1 smd mask+1: 1(0,0)
  Top Layer keep-out circle w1.678: c0,0 r0.75
FP-73252-0161_CONN_RF_JACK-MFG#1 [mm]
  round 0.41 smd paste-1000 mask+0: 1(0,0)
  round 1.518 smd paste-1000 mask+0: 2(0.268,1.418)
  round 1.6 hole 1.6 unplated paste-1000 mask+0: ""(0,-3.58) ""(0,3.58)
  Top Layer region: 2.265,0.4 1.804,1.427 0.911,2.112 -0.201,2.291 -1.264,1.922 -2.024,1.091 -2.3,0 -2.024,-1.091 -1.264,-1.922 -0.201,-2.291 0.911,-2.112 1.804,-1.427 2.265,-0.4 2.265,-0.4 0.447,-0.4 0.211,-0.562 -0.074,-0.595 -0.342,-0.493 -0.532,-0.278 -0.6,0 -0.532,0.278 -0.342,0.493 -0.074,0.595 0.211,0.562 0.447,0.4 0.447,0.4
  silkscreen extent -2.95,-5.13 2.96,5.13, body extent -3.05,-5.23 3.06,5.23, height 0.25
FP-73252-0161_CONN_RF_JACK-MFG#2 [mm]
  round 0.41 smd: 1(0,0)
  round 1.518 smd: 2(0.268,1.418)
  round 1.6 hole 1.6 unplated: ""(0,-3.58) ""(0,3.58)
  Top Layer region: 2.265,0.4 1.804,1.427 0.911,2.112 -0.201,2.291 -1.264,1.922 -2.024,1.091 -2.3,0 -2.024,-1.091 -1.264,-1.922 -0.201,-2.291 0.911,-2.112 1.804,-1.427 2.265,-0.4 2.265,-0.4 0.447,-0.4 0.211,-0.562 -0.074,-0.595 -0.342,-0.493 -0.532,-0.278 -0.6,0 -0.532,0.278 -0.342,0.493 -0.074,0.595 0.211,0.562 0.447,0.4 0.447,0.4
  silkscreen extent -2.96,-5.13 2.95,5.13, body extent -3.05,-5.23 3.05,5.23, height 0.25
FP-2027180100_HDR76-MFG [mm]
  rrect100% 1.6x0.36 smd paste+0 mask+0: 1(2.4,7) 2(2.4,6.2) 3(2.4,5.4) 4(2.4,4.6) 5(2.4,3.8) 6(2.4,3) 7(2.4,2.2) 8(2.4,1.4) 9(2.4,0.6) 10(2.4,-0.2) 11(2.4,-1) 12(2.4,-1.8) 13(2.4,-2.6) 14(2.4,-3.4) 15(2.4,-4.2) 16(2.4,-5) 17(2.4,-5.8) 18(2.4,-6.6) 19(2.4,-7.4) 20(11.19,-7) 21(11.19,-6.2) 22(11.19,-5.4) 23(11.19,-4.6) 24(11.19,-3.8) 25(11.19,-3) 26(11.19,-2.2) 27(11.19,-1.4) 28(11.19,-0.6) 29(11.19,0.2) 30(11.19,1) 31(11.19,1.8) 32(11.19,2.6) 33(11.19,3.4) 34(11.19,4.2) 35(11.19,5) 36(11.19,5.8) 37(11.19,6.6) 38(11.19,7.4) 39(5.33,7) 40(5.33,6.2) 41(5.33,5.4) 42(5.33,4.6) 43(5.33,3.8) 44(5.33,3) 45(5.33,2.2) 46(5.33,1.4) 47(5.33,0.6) 48(5.33,-0.2) 49(5.33,-1) 50(5.33,-1.8) 51(5.33,-2.6) 52(5.33,-3.4) 53(5.33,-4.2) 54(5.33,-5) 55(5.33,-5.8) 56(5.33,-6.6) 57(5.33,-7.4) 58(8.26,-7) 59(8.26,-6.2) 60(8.26,-5.4) 61(8.26,-4.6) 62(8.26,-3.8) 63(8.26,-3) 64(8.26,-2.2) 65(8.26,-1.4) 66(8.26,-0.6) 67(8.26,0.2) 68(8.26,1) 69(8.26,1.8) 70(8.26,2.6) 71(8.26,3.4) 72(8.26,4.2) 73(8.26,5) 74(8.26,5.8) 75(8.26,6.6) 76(8.26,7.4)
  rrect10% 0.96x1.32 smd paste+0 mask+0: 77(11.19,8.69) 78(-11.12,8.45) 81(-11.12,-8.45) 82(11.19,-8.69)
  round 3 hole 1.55 paste-1000 mask+0: 79(-9.1,8.4) 80(-9.1,-8.4)
  silkscreen extent -11.73,-9.23 11.73,11.07, body extent -11.83,-10 12.09,10, height 0.25
FP-2031431350_CAGE_QSFP-DD-MFG [mm]
  rrect5% 2x4 hole 1.05: 1(9.5,22.385) 2(-9.5,17.885) 3(9.5,13.385) 4(-9.5,8.885) 5(9.5,4.385) 6(-9.5,-0.115) 7(9.5,-4.615) 8(-9.5,-9.115) 9(9.5,-15.315) 10(-9.5,-19.815)
  silkscreen extent -10.3,-35.79 12.83,23.37, body extent -10.6,-35.88 10.6,35.89, height 0.25
FP-FT4232HL-REEL_LQFP64-MFG [mm]
  rrect33% 1.65x0.3 smd paste+0 mask+0: 1(-5.575,3.75)
  rrect100% 1.65x0.3 smd paste+0 mask+0: 2(-5.575,3.25) 3(-5.575,2.75) 4(-5.575,2.25) 5(-5.575,1.75) 6(-5.575,1.25) 7(-5.575,0.75) 8(-5.575,0.25) 9(-5.575,-0.25) 10(-5.575,-0.75) 11(-5.575,-1.25) 12(-5.575,-1.75) 13(-5.575,-2.25) 14(-5.575,-2.75) 15(-5.575,-3.25) 16(-5.575,-3.75) 33(5.575,-3.75) 34(5.575,-3.25) 35(5.575,-2.75) 36(5.575,-2.25) 37(5.575,-1.75) 38(5.575,-1.25) 39(5.575,-0.75) 40(5.575,-0.25) 41(5.575,0.25) 42(5.575,0.75) 43(5.575,1.25) 44(5.575,1.75) 45(5.575,2.25) 46(5.575,2.75) 47(5.575,3.25) 48(5.575,3.75)
  rrect100% 0.3x1.65 smd paste+0 mask+0: 17(-3.75,-5.575) 18(-3.25,-5.575) 19(-2.75,-5.575) 20(-2.25,-5.575) 21(-1.75,-5.575) 22(-1.25,-5.575) 23(-0.75,-5.575) 24(-0.25,-5.575) 25(0.25,-5.575) 26(0.75,-5.575) 27(1.25,-5.575) 28(1.75,-5.575) 29(2.25,-5.575) 30(2.75,-5.575) 31(3.25,-5.575) 32(3.75,-5.575) 49(3.75,5.575) 50(3.25,5.575) 51(2.75,5.575) 52(2.25,5.575) 53(1.75,5.575) 54(1.25,5.575) 55(0.75,5.575) 56(0.25,5.575) 57(-0.25,5.575) 58(-0.75,5.575) 59(-1.25,5.575) 60(-1.75,5.575) 61(-2.25,5.575) 62(-2.75,5.575) 63(-3.25,5.575) 64(-3.75,5.575)
  silkscreen extent -7.12,-5.05 5.05,5.05, body extent -6.5,-6.5 6.5,6.5, height 0.25
H+S_1X8A_81_MXP-S50-0-2_111N [mm] "Huber+Suhner"
  round 0.7 smd: 1(-14,0) 2(-10,0) 3(-6,0) 4(-2,0) 5(2,0) 6(6,0) 7(10,0) 8(14,0)
  round 1.65 hole 1.15 paste+0: 9(16.65,0) 10(0,2.18) 11(-17.08,0)
  Top Layer region: 577 vertices and 0 holes, not listed, extent -18.269,-2.829 17.349,2.845
  silkscreen extent -20.8,-5.3 20.8,5.3, body extent -17.5,-2.59 17.09,2.57, height 6.8
Label_650x200 [mil] "Thermal Transfer Label"
  round 1 on Mech13: 0(0,0)
  silkscreen extent -325,-100 325,100, body extent -325,-100 325,100, height 1
LG_M67K_Green [mm] "SMD, 2-Leads, Body 2x1.4mm, Pitch 2mm"
  rect 0.8x1 smd: 1(-1,0) 2(1,0)
  silkscreen extent -2.1,-1 1.05,1, body extent -1.05,-0.75 1.05,0.75, height 1.4
LTST-C150_1206_Green [mm] "SMD, 2-Leads, Body 1.6x3.2mm"
  rect 1.5x1.5 smd: 1(-1.75,0) 2(1.75,0)
  silkscreen extent -3.3,-1.15 2.65,1.15, body extent -1.65,-0.85 1.65,0.85, height 1.2
Molex_0565790576 [mm] "Receptacle, USB Mini-AB, 0.8mm, 5x1, R/A, SMT"
  rrect20% 0.5x2.25 smd: 1(-1.6,6.225) 2(-0.8,6.225) 3(0,6.225) 4(0.8,6.225) 5(1.6,6.225)
  rrect5% 2.05x3.5 smd: 6(4.925,6.25) 9(-4.925,6.25)
  rrect5% 2.05x4 smd: 7(4.925,2) 8(-4.925,2)
  Top Layer keep-out region: 3.1,0 3.1,1.2 -3.1,1.2 -3.1,0
  body extent -4.95,-2 4.95,7, height 3.96
Murata_NFM31P [mm] "SMD, 3-Leads, Body 3.2x1.6mm"
  rect 0.95x1 smd: 1(-1.725,0) 3(1.725,0)
  rect 1x0.7 smd: 2(0,0.65) 2(0,-0.65)
  silkscreen extent -2.59,-1.2 2.59,1.2, body extent -1.7,-0.9 1.7,0.9, height 1.5
"NY PMS 440 0025 PH" [mm] "4-40 nylon screw and mounting hole"
  round 8 hole 3.2 unplated: 1(0,0)
  body extent -3.3,-3.3 3.3,3.3, height 2.69
PW0016A_N [mm] "TSOP, 16-Leads, Body 5x4.4mm, Pitch 0.65mm, IPC Medium Density"
  oval 1.4x0.45 smd: 1(-2.95,2.275) 2(-2.95,1.625) 3(-2.95,0.975) 4(-2.95,0.325) 5(-2.95,-0.325) 6(-2.95,-0.975) 7(-2.95,-1.625) 8(-2.95,-2.275) 9(2.95,-2.275) 10(2.95,-1.625) 11(2.95,-0.975) 12(2.95,-0.325) 13(2.95,0.325) 14(2.95,0.975) 15(2.95,1.625) 16(2.95,2.275)
  silkscreen extent -3.5,-2.55 1.85,2.75, body extent -3.21,-2.5 3.21,2.5, height 1
RGY0020A [mm] "QFN, 20-Leads, Body 4.5x3.5mm, Pitch 0.5mm, Thermal Pad 3.05x2.05mm, TI Recommended"
  oval 0.24x0.6 smd: 1(-0.75,2.15) 10(-0.75,-2.15) 11(0.75,-2.15) 20(0.75,2.15)
  oval 0.6x0.24 smd: 2(-1.65,1.75) 3(-1.65,1.25) 4(-1.65,0.75) 5(-1.65,0.25) 6(-1.65,-0.25) 7(-1.65,-0.75) 8(-1.65,-1.25) 9(-1.65,-1.75) 12(1.65,-1.75) 13(1.65,-1.25) 14(1.65,-0.75) 15(1.65,-0.25) 16(1.65,0.25) 17(1.65,0.75) 18(1.65,1.25) 19(1.65,1.75)
  rect 2.05x3.05 smd: 21(0,0)
  silkscreen extent -1.97,-2.47 1.97,2.48, body extent -1.75,-2.25 1.75,2.25, height 1
RPS0012A [mm] "VQFN-12"
  rrect40% 0.2x0.2 smd: 1(-0.8,1) 5(-0.8,-1) 7(0.8,-1) 11(0.8,1)
  rrect40% 1.05x0.25 smd: 2(-0.775,0.5) 10(0.775,0.5)
  rrect40% 0.6x0.25 smd: 3(-1,0) 4(-1,-0.5) 8(1,-0.5) 9(1,0)
  rrect40% 0.25x0.8 smd: 6(0,-1.05)
  rrect40% 0.25x0.575 smd: 12(0,1.162)
  Top Layer region: -1.25,0.875 -1.269,0.879 -1.285,0.89 -1.296,0.906 -1.3,0.925 -1.3,0.925 -1.3,1.05 -1.296,1.069 -1.285,1.085 -1.269,1.096 -1.25,1.1 -1.25,1.1 -0.95,1.1 -0.95,1.4 -0.946,1.419 -0.935,1.435 -0.919,1.446 -0.9,1.45 -0.9,1.45 -0.6,1.45 -0.581,1.446 -0.565,1.435 -0.554,1.419 -0.55,1.4 -0.55,1.4 -0.55,0.925 -0.554,0.906 -0.565,0.89 -0.581,0.879 -0.6,0.875 -0.6,0.875
  Top Layer region: 1.25,0.875 1.269,0.879 1.285,0.89 1.296,0.906 1.3,0.925 1.3,0.925 1.3,1.05 1.296,1.069 1.285,1.085 1.269,1.096 1.25,1.1 1.25,1.1 0.95,1.1 0.95,1.4 0.946,1.419 0.935,1.435 0.919,1.446 0.9,1.45 0.9,1.45 0.6,1.45 0.581,1.446 0.565,1.435 0.554,1.419 0.55,1.4 0.55,1.4 0.55,0.925 0.554,0.906 0.565,0.89 0.581,0.879 0.6,0.875 0.6,0.875
  Top Layer region: -1.25,-0.875 -1.269,-0.879 -1.285,-0.89 -1.296,-0.906 -1.3,-0.925 -1.3,-0.925 -1.3,-1.05 -1.296,-1.069 -1.285,-1.085 -1.269,-1.096 -1.25,-1.1 -1.25,-1.1 -0.95,-1.1 -0.95,-1.4 -0.946,-1.419 -0.935,-1.435 -0.919,-1.446 -0.9,-1.45 -0.9,-1.45 -0.6,-1.45 -0.581,-1.446 -0.565,-1.435 -0.554,-1.419 -0.55,-1.4 -0.55,-1.4 -0.55,-0.925 -0.554,-0.906 -0.565,-0.89 -0.581,-0.879 -0.6,-0.875 -0.6,-0.875
  Top Layer region: 1.25,-0.875 1.269,-0.879 1.285,-0.89 1.296,-0.906 1.3,-0.925 1.3,-0.925 1.3,-1.05 1.296,-1.069 1.285,-1.085 1.269,-1.096 1.25,-1.1 1.25,-1.1 0.95,-1.1 0.95,-1.4 0.946,-1.419 0.935,-1.435 0.919,-1.446 0.9,-1.45 0.9,-1.45 0.6,-1.45 0.581,-1.446 0.565,-1.435 0.554,-1.419 0.55,-1.4 0.55,-1.4 0.55,-0.925 0.554,-0.906 0.565,-0.89 0.581,-0.879 0.6,-0.875 0.6,-0.875
  body extent -1.15,-1.3 1.15,1.3, height 1
RQY0009A-MFG [mm]
  rrect40% 0.25x0.55 smd: 1(-0.5,1.175) 4(-0.5,-1.175) 5(0,-1.175) 6(0.5,-1.175) 8(0.5,1.175) 9(0,1.175)
  rrect50% 0.95x0.2 smd: 2(-0.475,0.4) 3(-0.475,-0.4) 7(0.475,0)
  silkscreen extent -1.02,-1.3 1.03,2.15, body extent -1.05,-1.55 1.05,1.55, height 0.25
Samtec_HTSW-102-09-x-S [mm] "Header, 2x1, 2.54mm, TH"
  rect 1.55x1.55 hole 1.02: 1(-1.27,0)
  round 1.55 hole 1.02: 2(1.27,0)
  silkscreen extent -2.54,-1.24 2.54,1.6, body extent -2.54,-1.24 2.54,1.24, height 8.38
Samtec_HTSW-103-07-G-S [mm] "Samtec 100mil, 1x3, 230 mil above insulator"
  rrect6% 1.65x1.65 hole 1.016: 1(-2.54,0)
  round 1.65 hole 1.016: 2(0,0) 3(2.54,0)
  silkscreen extent -4.57,-1.27 3.81,1.27, body extent -3.81,-1.27 3.81,1.27, height 8.38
